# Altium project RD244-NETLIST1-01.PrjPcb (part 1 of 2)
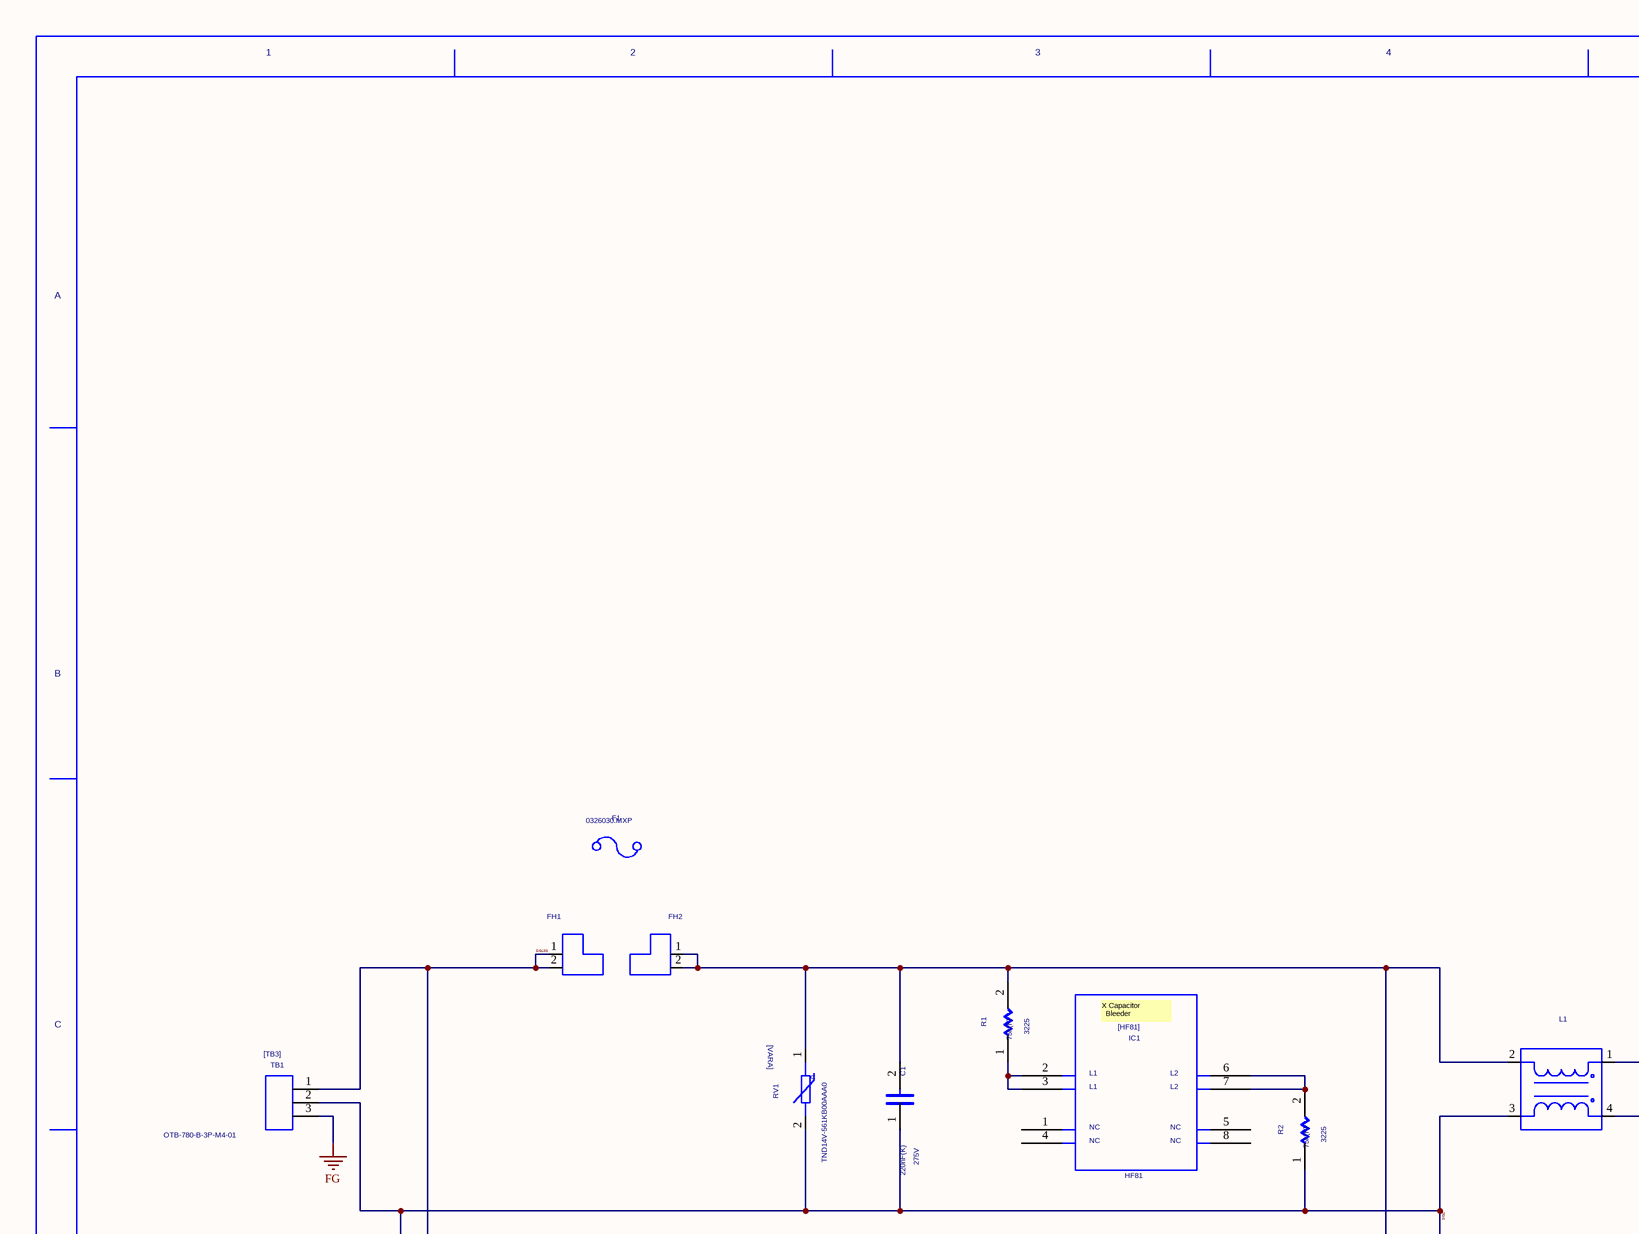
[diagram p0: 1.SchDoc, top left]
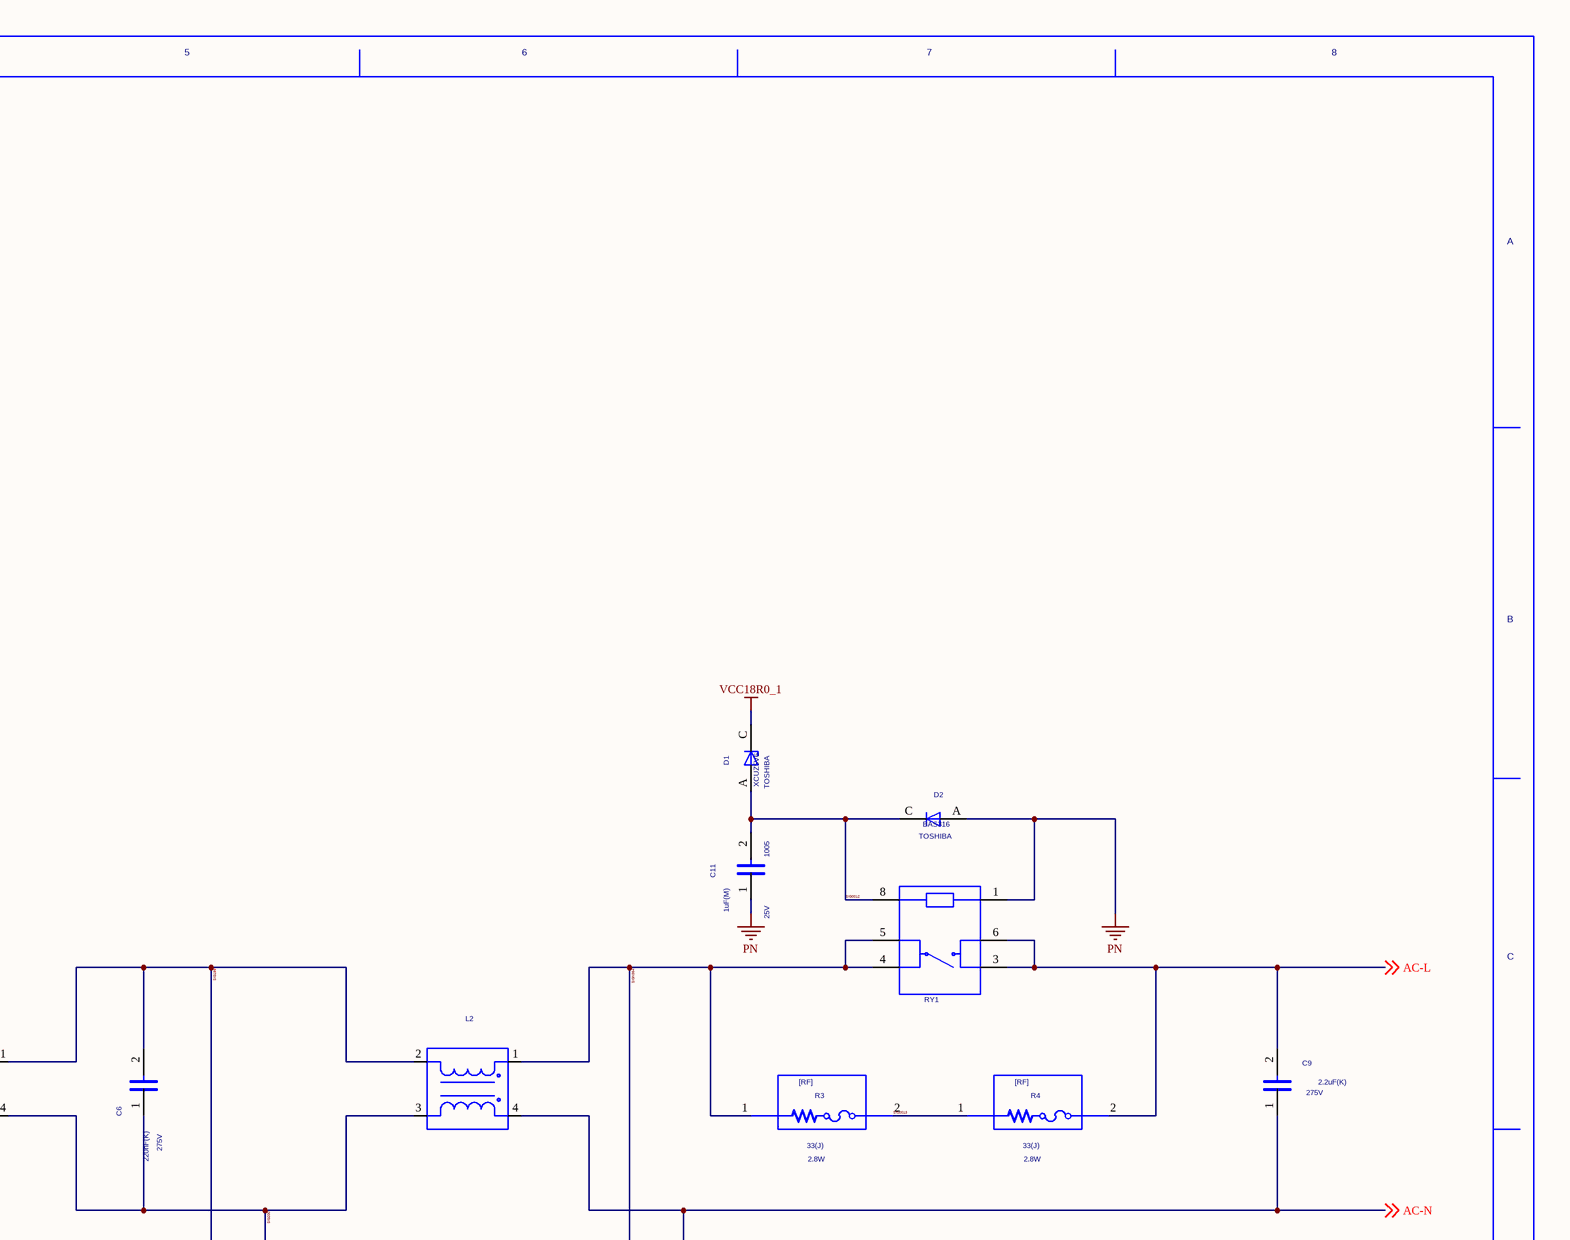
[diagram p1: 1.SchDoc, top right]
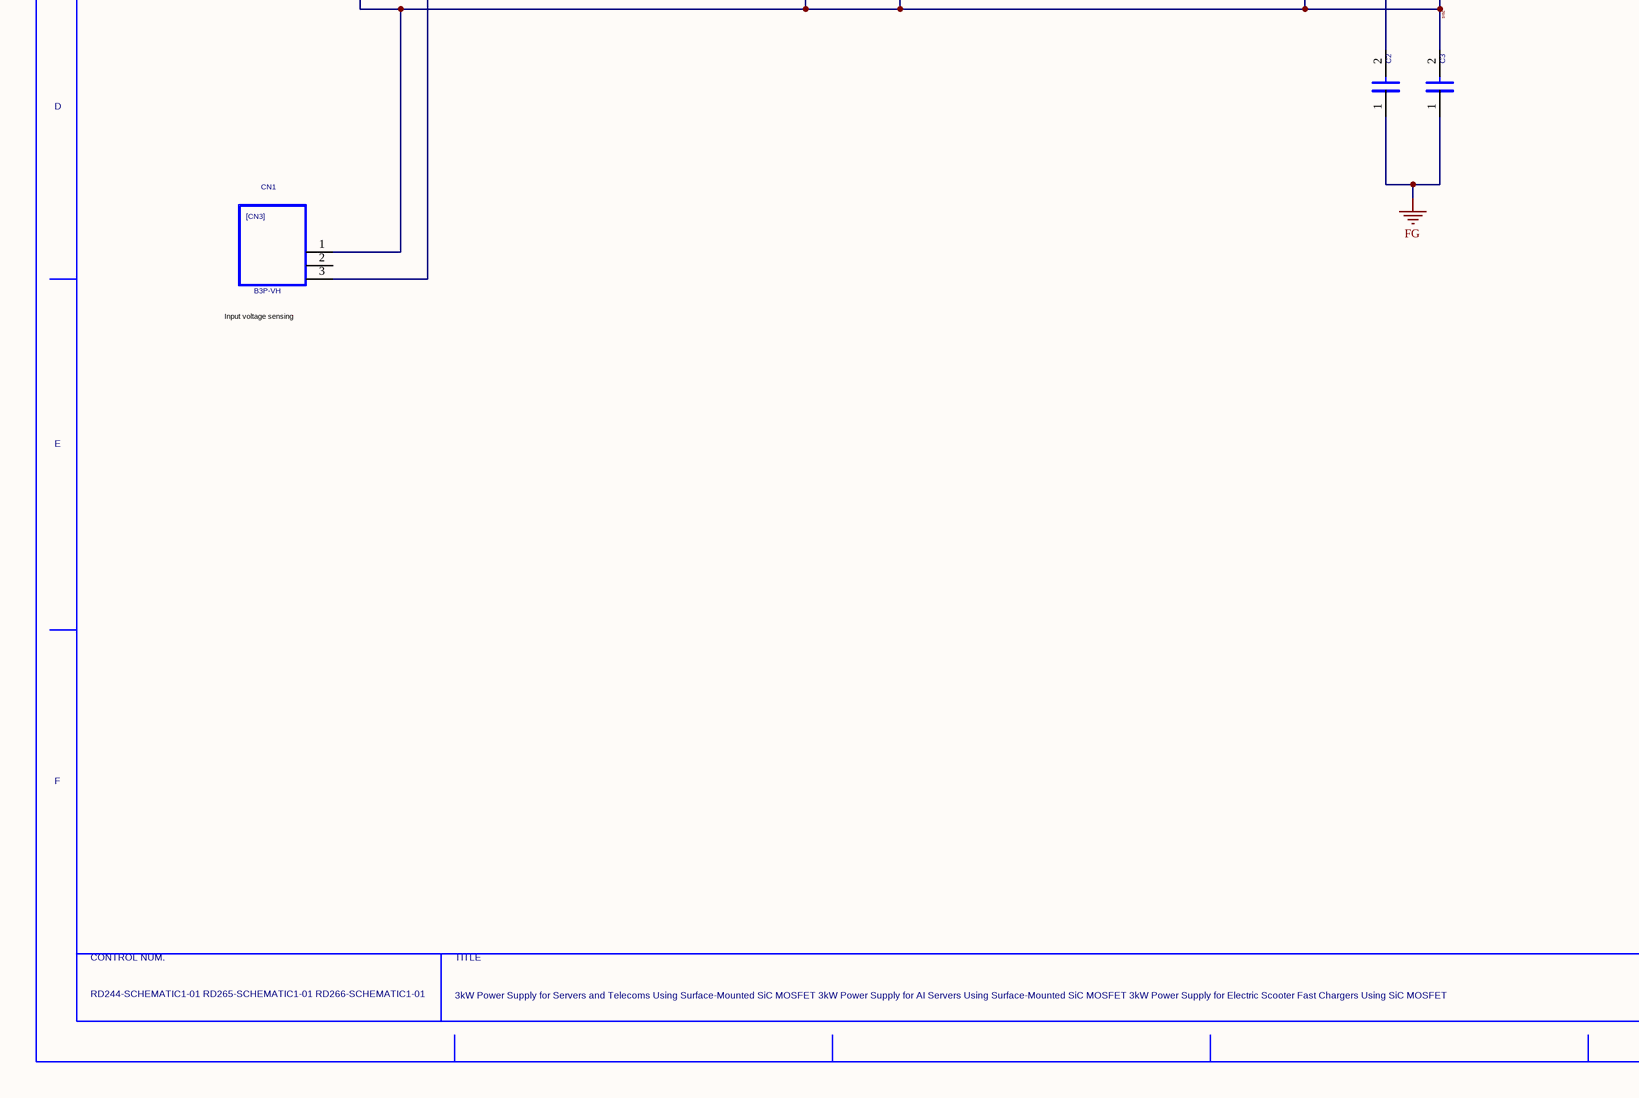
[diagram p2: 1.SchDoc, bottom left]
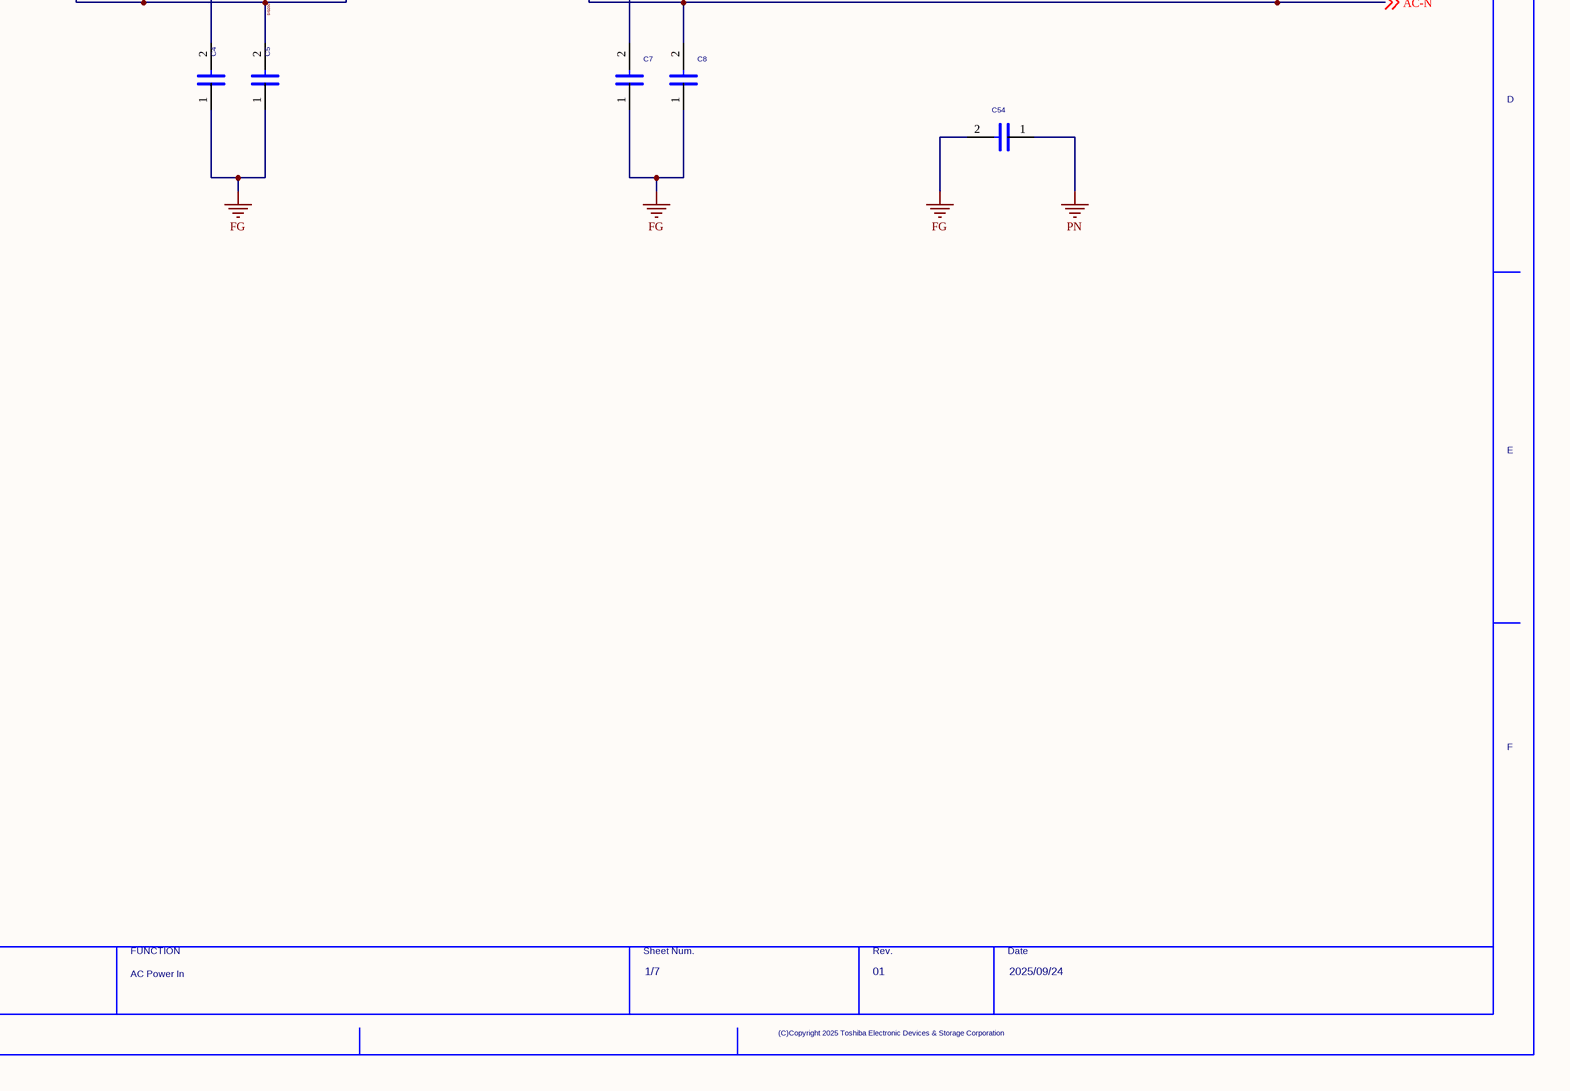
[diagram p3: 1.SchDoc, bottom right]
7 sheets, 392 parts. Net scope: global (net labels, ports and power ports of the same name join across sheets).
Sheets:
  1.SchDoc
  2.SchDoc
  3.SchDoc
  4.SchDoc
  5.SchDoc
  6.SchDoc
  7.SchDoc

## Sheet 1.SchDoc
size 609 x 444 mm

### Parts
(Parts that share a designator on the sheet are numbered #1, #2 ... from top to bottom, then left to right.)
C1  VAL1: 220nF(K)  VAL2: 275V  (hidden comment: C)
C2  DE2B3SA101KA3BT02F  (value not drawn)
C3  DE2B3SA101KA3BT02F  (value not drawn)
C4  DE2E3SA222MN3AT02F  (value not drawn)
C5  DE2E3SA222MN3AT02F  (value not drawn)
C6  VAL1: 220nF(K)  VAL2: 275V  (hidden comment: C)
C7  DE2E3SA222MN3AT02F  (value not drawn)
C8  DE2E3SA222MN3AT02F  (value not drawn)
C9  VAL1: 2.2uF(K)  VAL2: 275V  (hidden comment: C)
C11  VAL1: 1uF(M)  VAL2: 25V  SIZECODESMD: 1005  (hidden comment: C)
C54  DE2B3SA221KA3BT02F  (value not drawn)
CN1  VAL3: B3P-VH  (hidden comment: CN3)
D1  USERCOMPTEXT3: TOSHIBA  VAL3: XCUZ5V6  (hidden comment: ZenerDiode_USC-01)
D2  USERCOMPTEXT3: TOSHIBA  VAL3: BAS316  (hidden comment: D)
F1  (no value)
FH1  01220083Z  (value not drawn)
FH2  01220083Z  (value not drawn)
IC1  VAL3: HF81  (hidden comment: L81)
L1  LDFW021252YBUV0E  (value not drawn)
L2  LDFW021252YBUV0E  (value not drawn)
R1  VAL1: 75k(F)  SIZECODESMD: 3225  (hidden comment: R)
R2  VAL1: 75k(F)  SIZECODESMD: 3225  (hidden comment: R)
R3  VAL1: 33(J)  VAL2: 2.8W  (hidden comment: Y5JA-330JPTL3_5)
R4  VAL1: 33(J)  VAL2: 2.8W  (hidden comment: Y5JA-330JPTL3_5)
RV1  VAL3: TND14V-561KB00AAA0  (hidden comment: VARA)
RY1  G2RL-1A-E2-CV-HA  (value not drawn)
TB1  VAL3: OTB-780-B-3P-M4-01  (hidden comment: TB3)
U?#1  DATE: 2025/09/24  DRAWINGNUMBER: RD244-SCHEMATIC1-01 / RD265-SCHEMATIC1-01 / RD266-SCHEMATIC1-01  TITLE: 3kW Power Supply for Servers and Telecoms Using Surface-Mounted SiC MOSFET / 3kW Power Supply for AI Servers Using Surface-Mounted SiC MOSFET / 3kW Power Supply for Electric Scooter Fast Chargers Using SiC MOSFET  FUNCTION: AC Power In  SHEETNUMBER: 1/7  REVISION: 01  (hidden comment: WAKU_DEF_A3_1)

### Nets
FG: C2.1 C3.1 C4.1 C5.1 C7.1 C8.1 C54.2 TB1.3
PN: C11.1 C54.1 D2.A RY1.1
VCC18R0_1: D1.C
AC-L: C9.2 R4.2 RY1.3 RY1.6 ; off-sheet AC-L
AC-N: C8.2 C9.1 L2.4 ; off-sheet AC-N
SIG1: C1.2 C2.2 FH2.1 FH2.2 L1.2 R1.2 RV1.1
SIG2: C1.1 C3.2 CN1.1 L1.3 R2.1 RV1.2 TB1.2
SIG9: IC1.2 IC1.3 R1.1
SIG10: IC1.6 IC1.7 R2.2
SIG0012: C11.2 D1.A D2.C RY1.8
SIG0013: R3.2 R4.1
SIG193: CN1.3 FH1.1 FH1.2 TB1.1
SIG199: C4.2 C6.2 L1.1 L2.2
SIG200: C5.2 C6.1 L1.4 L2.3
SIGN364: C7.2 L2.1 R3.1 RY1.4 RY1.5

Not connected (* = marked no-connect by the designer): CN1 2; IC1 1 4 5 8

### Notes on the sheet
- (near CN1) Input voltage sensing

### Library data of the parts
C1 C6 = C_Dup2: OriginalSymbolOrigin: (2540,7620); COMP: PRT_17; MAXGCOUNT: 1; SIZECODESMD: DIP; SAVECOUNT: 0
C2 C3 = DE2B3SA101KA3BT02F: VAL1: 100pF; VAL2: 250V; TIME: 18:06:52; UPDATEUSER: t6860224; SAVECOUNT: 1; OriginalSymbolOrigin: (2540,7620); SIZECODESMD: DIP; CHIPSIZE: リードピッチ7.5mm品希望
C4 C7 C8 = DE2E3SA222MN3AT02F: VAL1: 2.2nF(M); VAL2: 250V; TIME: 18:04:40; UPDATEUSER: t6860224; UPDATETIME: 18:05:46; SAVECOUNT: 2; OriginalSymbolOrigin: (2540,7620); CHIPSIZE: リードピッチ7.5mm品希望; MAXGCOUNT: 1; SIZECODESMD: DIP
C5 = DE2E3SA222MN3AT02F: SQ_PART_MODEL: CON_2.2N; VAL1: 2.2nF(M); VAL2: 250V; TIME: 18:04:40; UPDATEUSER: t6860224; UPDATETIME: 18:05:46; SAVECOUNT: 2; OriginalSymbolOrigin: (2540,7620); CHIPSIZE: リードピッチ7.5mm品希望; MAXGCOUNT: 1; SIZECODESMD: DIP; ADSCNVFLAG: ON
C9 = C_Dup2: OriginalSymbolOrigin: (2540,7620); COMP: PRT_18; MAXGCOUNT: 1; SIZECODESMD: DIP; SAVECOUNT: 0
C11 = C_Dup2: OriginalSymbolOrigin: (2540,7620); COMP: PRT_52; MAXGCOUNT: 1; SAVECOUNT: 0
C54 = DE2B3SA221KA3BT02F: VAL1: 220pF(K); VAL2: 250V; TIME: 18:06:26; UPDATEUSER: t6860224; SAVECOUNT: 1; OriginalSymbolOrigin: (2540,7620); SIZECODESMD: DIP
CN1 = CN3: OriginalSymbolOrigin: (2540,17780); USERCOMPTEXT3: ローカライズ; COMPONENTNAME: G36220401068_package; MAXGCOUNT: 1; COMP: G36220401068; ADSCNVFLAG: ON; SAVECOUNT: 0
D1 = ZENERDIODE_USC-01: SAVEAREA0: -4630,-153,17114,13055; TIME: 14:49:55; UPDATEUSER: t4887876; UPDATETIME: 08:23:49; SAVECOUNT: 9; VAL1: 5.6V; OriginalSymbolOrigin: (5080,5080); MAXGCOUNT: 1; ADSCNVFLAG: ON; ADSCOMPONENTNAME: D_ZD
D2 = D_Dup1: SAVEAREA0: -225,-91,12804,7836; SAVECOUNT: 3; TIME: 14:49:55; UPDATEUSER: 19870035; UPDATETIME: 14:20:16; OriginalSymbolOrigin: (5080,5080); USERCOMPTEXT2: 100V,0.25A; COMP: PRT_26; MAXGCOUNT: 1
F1 = 0326030.MXP: PCBCELLNAME: F; SAVECOUNT: 7; SAVEAREA0: -525,-4690,15446,5013; DEVICENAME: F0805B2R00FWTR; VAL1: 250VAC; VAL2: 30A SlowBlow; TIME: 10:50:48; UPDATEUSER: t4887876; UPDATETIME: 10:51:07; OriginalSymbolOrigin: (3048,3166)
FH1 FH2 = 01220083Z: VAL1: 250V; VAL2: 30A; TIME: 10:48:22; UPDATEUSER: t4887876; UPDATETIME: 10:49:44; SAVECOUNT: 3; OriginalSymbolOrigin: (7620,10160)
IC1 = L81: SAVEAREA0: -12429,-3512,55842,41521; TIME: 18:31:00; UPDATEUSER: cae; UPDATETIME: 11:10:50; SAVECOUNT: 13; OriginalSymbolOrigin: (7620,35560); COMP: PRT_45
L1 L2 = LDFW021252YBUV0E: DEVICENAME: DLW21HN670SQ2; SAVEAREA0: -21350,-26515,41553,39372; TIME: 11:39:40; UPDATEUSER: t4887876; UPDATETIME: 20:09:21; SAVECOUNT: 7; VAL1: 8.1mH; VAL2: 21A; OriginalSymbolOrigin: (2540,12700)
R1 R2 = R_Dup2: VAL2: 500mW; OriginalSymbolOrigin: (5080,5080); COMP: PRT_23; MAXGCOUNT: 1; SAVECOUNT: 0
R3 R4 = Y5JA-330JPTL3_5: TIME: 16:26:39; UPDATEUSER: t4887876; UPDATETIME: 20:40:35; SAVECOUNT: 5; OriginalSymbolOrigin: (-1270,12700); MAXGCOUNT: 1; CHIPSIZE: 13x9xH25.5
RV1 = VARA: SAVEAREA0: -9950,-8554,25168,13619; SAVECOUNT: 12; TIME: 09:56:50; UPDATEUSER: tomizawa-y; OriginalSymbolOrigin: (2540,5080); COMP: PRT_37; VAL1: 560V; MAXGCOUNT: 1
RY1 = G2RL-1A-E2-CV-HA: TIME: 17:19:14; UPDATEUSER: t4887876; UPDATETIME: 19:21:58; SAVECOUNT: 7; COMP: G2RL-1A-E2-CV-HA_DC12; OriginalSymbolOrigin: (5080,20320); USERCOMPTEXT1: 23A; MAXGCOUNT: 1; SAVEAREA0: -9347,-440,34039,23986
TB1 = TB3: SAVEAREA0: -8260,-205,20967,17940; TIME: 13:41:39; UPDATEUSER: 19990028; UPDATETIME: 11:31:50; SAVECOUNT: 4; OriginalSymbolOrigin: (2540,12700); USERCOMPTEXT3: ローカライズ; MAXGCOUNT: 1; COMP: K29S000A; ADSCNVFLAG: ON
U?#1 = WAKU_DEF_A3_1: PLOTTIME: HH:MM; SAVEAREA0: 96913,-567914,509243,-368858; TIME: 10:19:22; UPDATEUSER: t5459927; UPDATETIME: 13:12:48; SAVECOUNT: 3; ZONEOFFSETX: 36; ZONEOFFSETY: -24; OriginalSymbolOrigin: (12700,-12700); SHTSAVECOUNT: 118; PAGENUMBER: 1; DESIGNED: TOSHIBA

## Sheet 2.SchDoc
size 609 x 444 mm
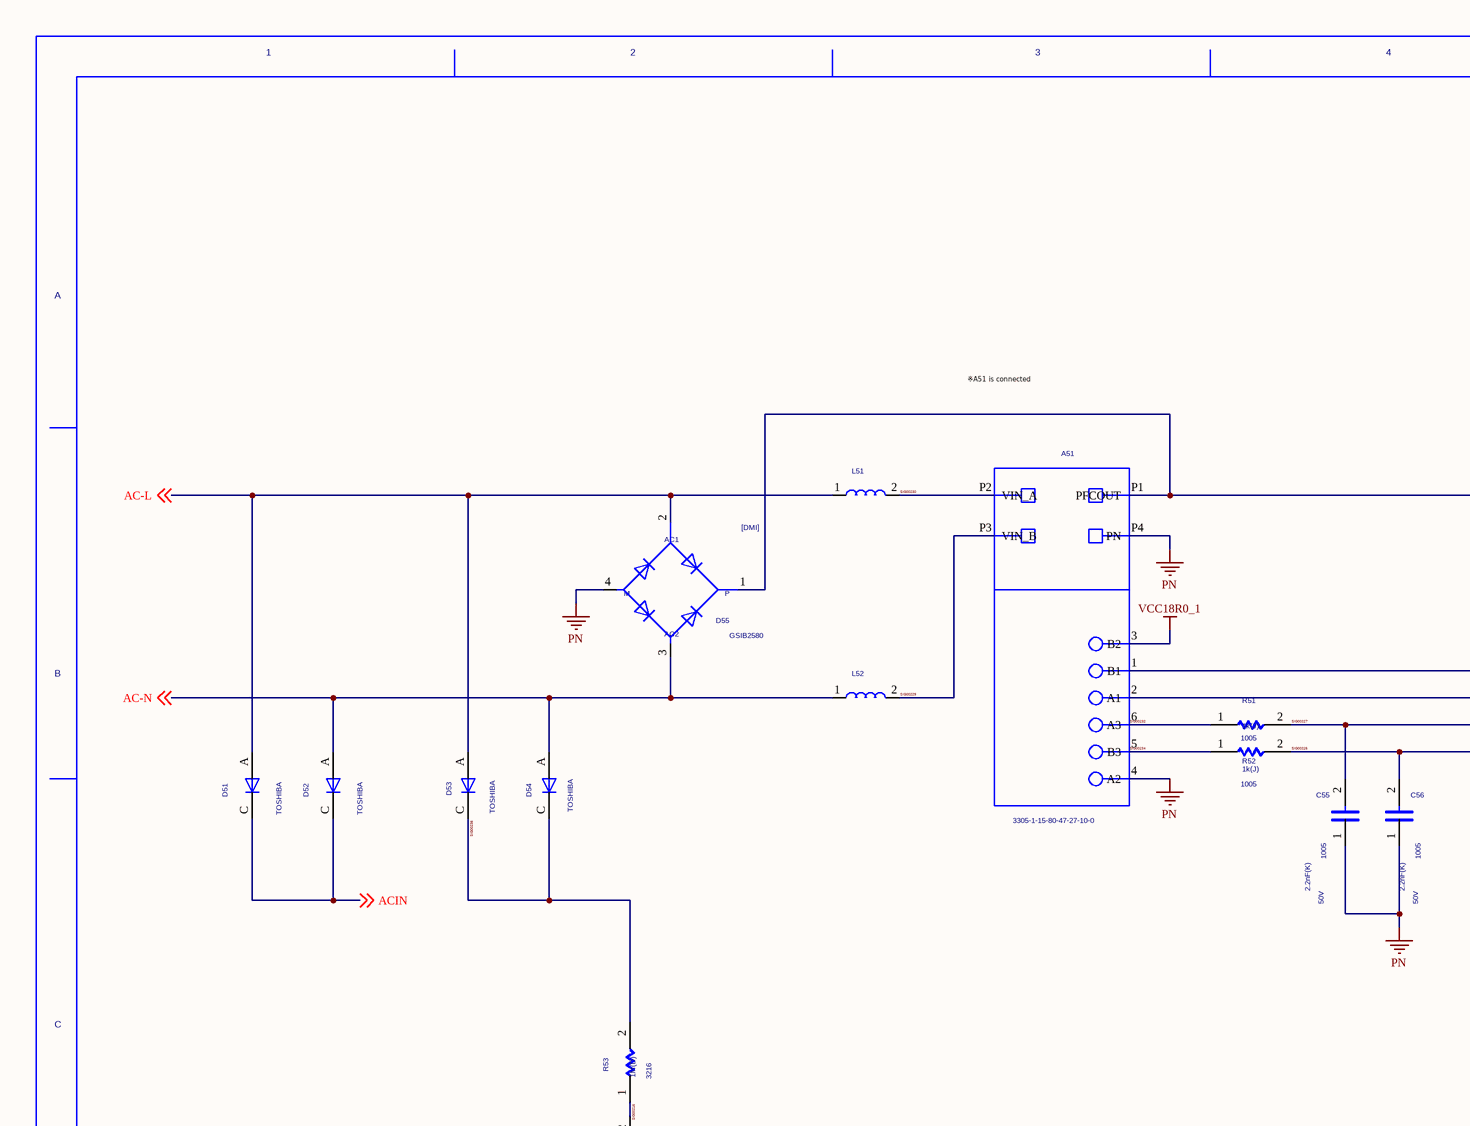
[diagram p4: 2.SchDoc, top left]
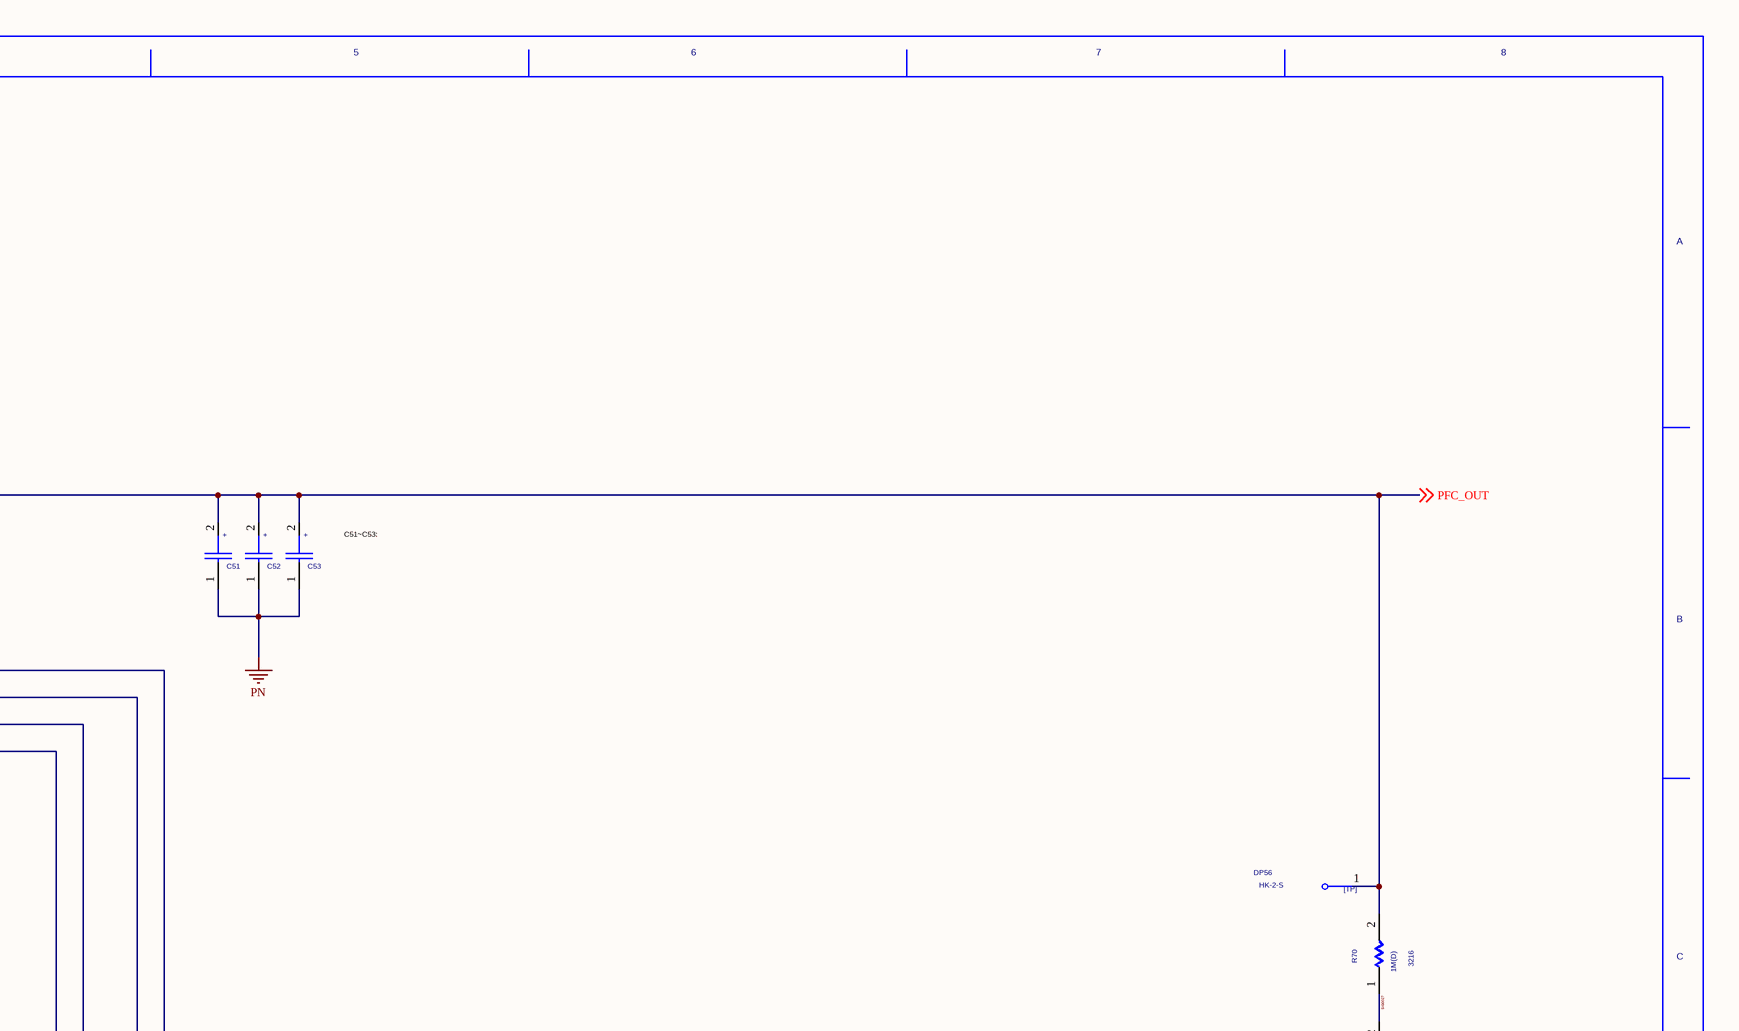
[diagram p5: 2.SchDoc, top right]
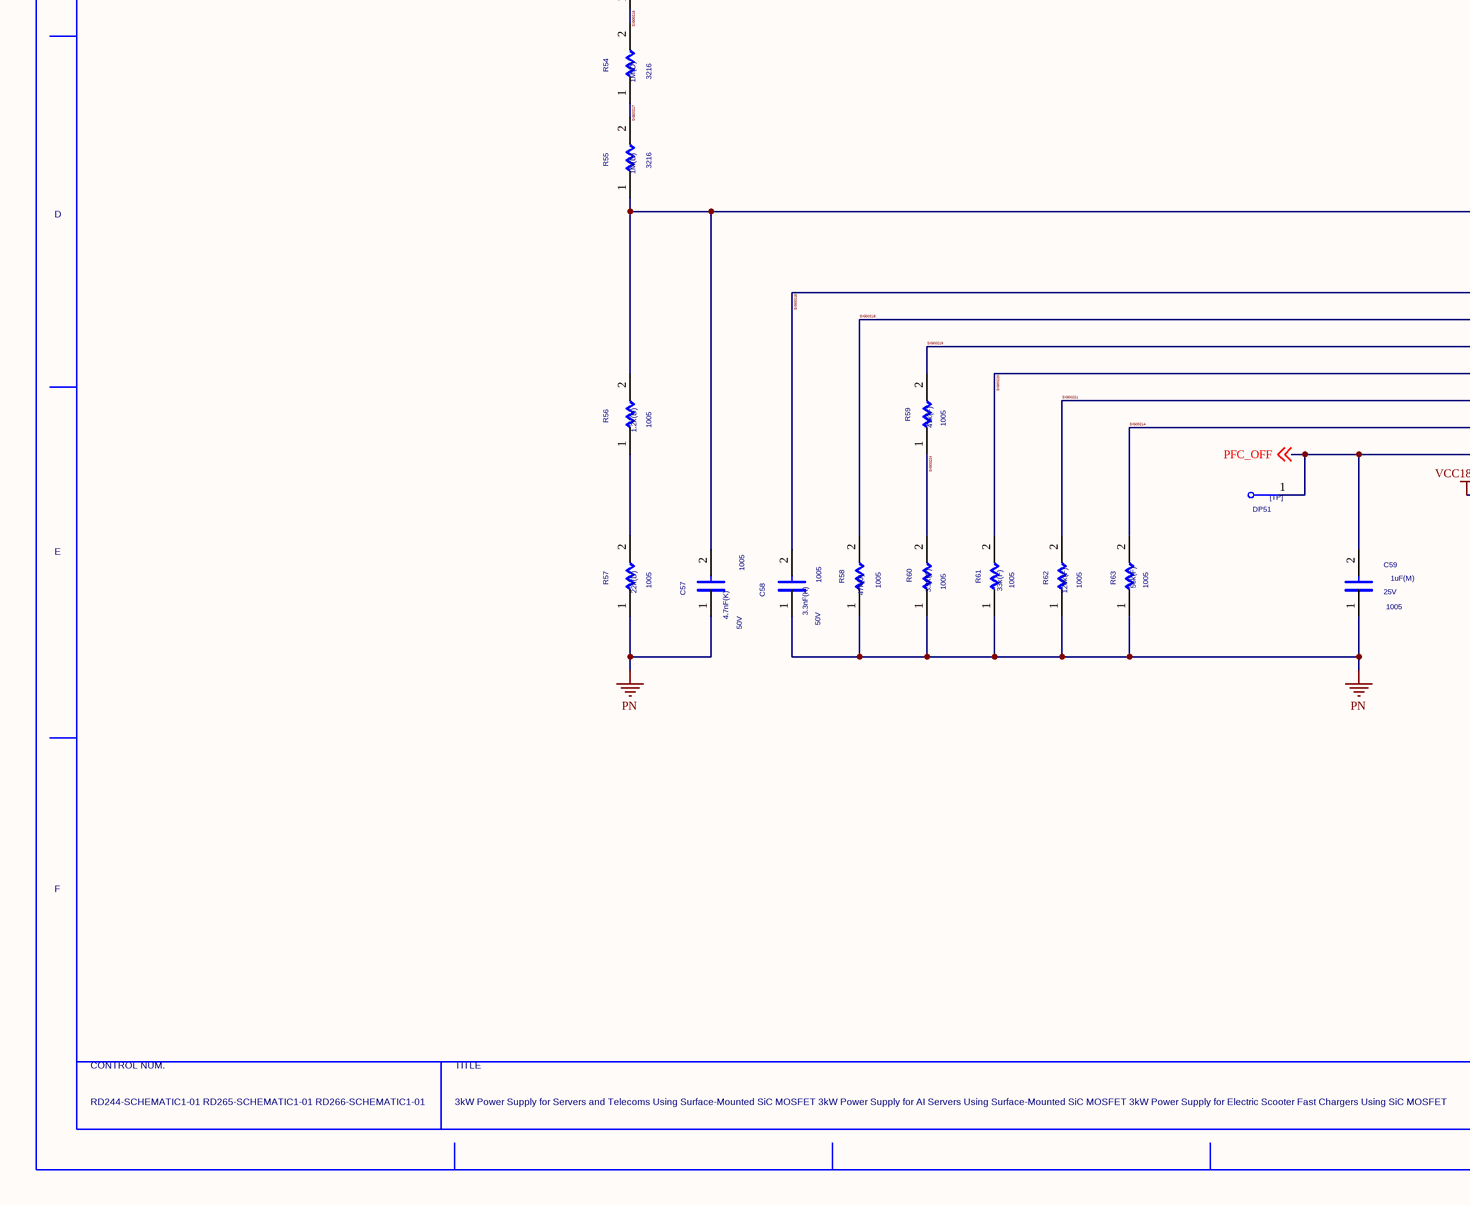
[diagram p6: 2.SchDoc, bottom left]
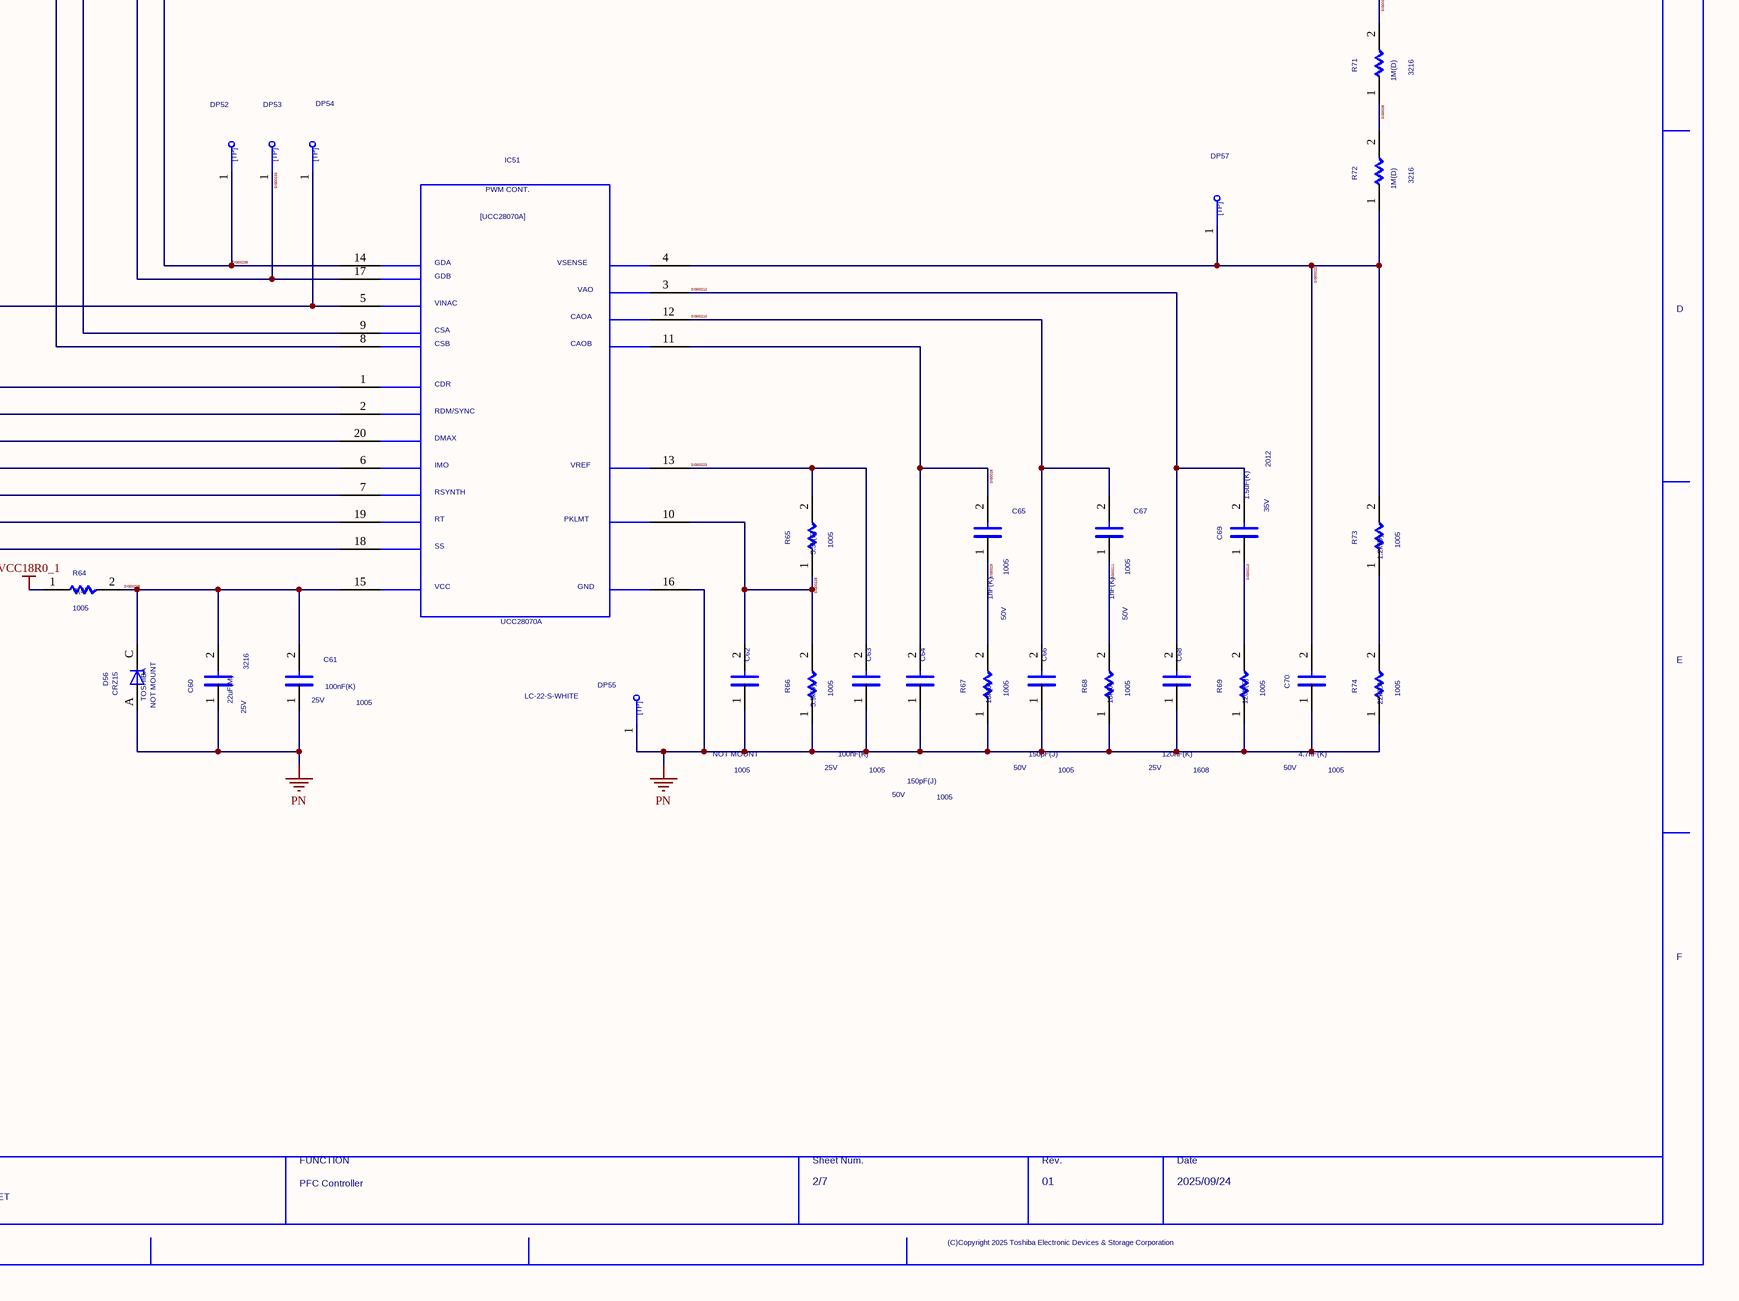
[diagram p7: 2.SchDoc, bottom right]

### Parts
(Parts that share a designator on the sheet are numbered #1, #2 ... from top to bottom, then left to right.)
A51  VAL3: 3305-1-15-80-47-27-10-0  (hidden comment: RD-244_PFC_UNIT1)
C51  EKHE421VSN102MA45Z  (value not drawn)
C52  EKHE421VSN102MA45Z  (value not drawn)
C53  EKHE421VSN102MA45Z  (value not drawn)
C55  VAL1: 2.2nF(K)  VAL2: 50V  SIZECODESMD: 1005  (hidden comment: C)
C56  VAL1: 2.2nF(K)  VAL2: 50V  SIZECODESMD: 1005  (hidden comment: C)
C57  VAL1: 4.7nF(K)  VAL2: 50V  SIZECODESMD: 1005  (hidden comment: C)
C58  VAL1: 3.3nF(K)  VAL2: 50V  SIZECODESMD: 1005  (hidden comment: C)
C59  VAL1: 1uF(M)  VAL2: 25V  SIZECODESMD: 1005  (hidden comment: C)
C60  VAL1: 22uF(M)  VAL2: 25V  SIZECODESMD: 3216  (hidden comment: C)
C61  VAL1: 100nF(K)  VAL2: 25V  SIZECODESMD: 1005  (hidden comment: C)
C62  NOTMOUNT: NOT MOUNT  SIZECODESMD: 1005  (hidden comment: C)
C63  VAL1: 100nF(K)  VAL2: 25V  SIZECODESMD: 1005  (hidden comment: C)
C64  VAL1: 150pF(J)  VAL2: 50V  SIZECODESMD: 1005  (hidden comment: C)
C65  VAL1: 1nF(K)  VAL2: 50V  SIZECODESMD: 1005  (hidden comment: C)
C66  VAL1: 150pF(J)  VAL2: 50V  SIZECODESMD: 1005  (hidden comment: C)
C67  VAL1: 1nF(K)  VAL2: 50V  SIZECODESMD: 1005  (hidden comment: C)
C68  VAL1: 120nF(K)  VAL2: 25V  SIZECODESMD: 1608  (hidden comment: C)
C69  VAL1: 1.5uF(K)  VAL2: 35V  SIZECODESMD: 2012  (hidden comment: GRM21BC71E106KE01)
C70  VAL1: 4.7nF(K)  VAL2: 50V  SIZECODESMD: 1005  (hidden comment: C)
D51  USERCOMPTEXT3: TOSHIBA  (hidden comment: CRG04A)
D52  USERCOMPTEXT3: TOSHIBA  (hidden comment: CRG04A)
D53  USERCOMPTEXT3: TOSHIBA  (hidden comment: CRG04A)
D54  USERCOMPTEXT3: TOSHIBA  (hidden comment: CRG04A)
D55  VAL3: GSIB2580  (hidden comment: DMI)
D56  NOTMOUNT: NOT MOUNT  USERCOMPTEXT3: TOSHIBA  VAL3: CRZ15  (hidden comment: ZD)
DP51  TP  (value not drawn)
DP52  TP  (value not drawn)
DP53  TP  (value not drawn)
DP54  TP  (value not drawn)
DP55  VAL3: LC-22-S-WHITE  (hidden comment: TP)
DP56  VAL3: HK-2-S  (hidden comment: TP)
DP57  TP  (value not drawn)
IC51  VAL3: UCC28070A  (hidden comment: L28070)
L51  TAM-30A131  (value not drawn)
L52  TAM-30A131  (value not drawn)
R51  VAL1: 1k(J)  SIZECODESMD: 1005  (hidden comment: R)
R52  VAL1: 1k(J)  SIZECODESMD: 1005  (hidden comment: R)
R53  VAL1: 1M(D)  SIZECODESMD: 3216  (hidden comment: R)
R54  VAL1: 1M(D)  SIZECODESMD: 3216  (hidden comment: R)
R55  VAL1: 1M(D)  SIZECODESMD: 3216  (hidden comment: R)
R56  VAL1: 1.2k(D)  SIZECODESMD: 1005  (hidden comment: R)
R57  VAL1: 22k(D)  SIZECODESMD: 1005  (hidden comment: R)
R58  VAL1: 47k(J)  SIZECODESMD: 1005  (hidden comment: R)
R59  VAL1: 47k(F)  SIZECODESMD: 1005  (hidden comment: R)
R60  VAL1: 3.3k(F)  SIZECODESMD: 1005  (hidden comment: R)
R61  VAL1: 33k(F)  SIZECODESMD: 1005  (hidden comment: R)
R62  VAL1: 120k(F)  SIZECODESMD: 1005  (hidden comment: R)
R63  VAL1: 56k(F)  SIZECODESMD: 1005  (hidden comment: R)
R64  VAL1: 1(J)  SIZECODESMD: 1005  (hidden comment: R)
R65  VAL1: 3.3k(F)  SIZECODESMD: 1005  (hidden comment: R)
R66  VAL1: 3.9k(J)  SIZECODESMD: 1005  (hidden comment: R)
R67  VAL1: 18k(J)  SIZECODESMD: 1005  (hidden comment: R)
R68  VAL1: 18k(J)  SIZECODESMD: 1005  (hidden comment: R)
R69  VAL1: 120k(F)  SIZECODESMD: 1005  (hidden comment: R)
R70  VAL1: 1M(D)  SIZECODESMD: 3216  (hidden comment: R)
R71  VAL1: 1M(D)  SIZECODESMD: 3216  (hidden comment: R)
R72  VAL1: 1M(D)  SIZECODESMD: 3216  (hidden comment: R)
R73  VAL1: 1.2k(D)  SIZECODESMD: 1005  (hidden comment: R)
R74  VAL1: 22k(D)  SIZECODESMD: 1005  (hidden comment: R)
U?#2  DATE: 2025/09/24  DRAWINGNUMBER: RD244-SCHEMATIC1-01 / RD265-SCHEMATIC1-01 / RD266-SCHEMATIC1-01  TITLE: 3kW Power Supply for Servers and Telecoms Using Surface-Mounted SiC MOSFET / 3kW Power Supply for AI Servers Using Surface-Mounted SiC MOSFET / 3kW Power Supply for Electric Scooter Fast Chargers Using SiC MOSFET  FUNCTION: PFC Controller  SHEETNUMBER: 2/7  REVISION: 01  (hidden comment: WAKU_DEF_A3_1)

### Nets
PN: A51.4(A2) A51.P4(PN) C51.1 C52.1 C53.1 C55.1 C56.1 C57.1 C58.1 C59.1 C60.1 C61.1 C62.1 C63.1 C64.1 C66.1 C68.1 C70.1 D55.4 D56.A DP55.1 IC51.16 R57.1 R58.1 R60.1 R61.1 R62.1 R63.1 R66.1 R67.1 R68.1 R69.1 R74.1
VCC18R0_1: A51.3(B2) R64.1
$BN000001: R73.1 R74.2
$BN000002: R56.1 R57.2
AC-L: D51.A D53.A D55.2 L51.1 ; off-sheet AC-L
AC-N: D52.A D54.A D55.3 L52.1 ; off-sheet AC-N
ACIN: D51.C D52.C ; off-sheet ACIN
PFC_OFF: C59.2 DP51.1 IC51.18 ; off-sheet PFC_OFF
PFC_OUT: A51.P1(PFCOUT) C51.2 C52.2 C53.2 D55.1 DP56.1 R70.2 ; off-sheet PFC_OUT
SIG0026: R71.1 R72.2
SIG0027: R70.1 R71.2
SIG0028: C64.2 C65.2 IC51.11
SIG0029: C65.1 R67.2
SIG62: C57.2 DP54.1 IC51.5 R55.1 R56.2
SIG00210: C66.2 C67.2 IC51.12
SIG00211: C67.1 R68.2
SIG00212: C68.2 C69.2 IC51.3
SIG00213: C69.1 R69.2
SIG00214: IC51.19 R63.2
SIG00215: IC51.2 R58.2
SIG00216: R53.1 R54.2
SIG00217: R54.1 R55.2
SIG00218: C58.2 IC51.1
SIG00219: IC51.20 R59.2
SIG00220: IC51.6 R61.2
SIG00221: IC51.7 R62.2
SIG00222: C70.2 DP57.1 IC51.4 R72.1 R73.2
SIG00223: C63.2 IC51.13 R65.2
SIG00224: R59.1 R60.2
SIG00225: C62.2 IC51.10 R65.1 R66.2
SIG00226: C56.2 IC51.8 R52.2
SIG00227: C55.2 IC51.9 R51.2
SIG00228: C60.2 C61.2 D56.C IC51.15 R64.2
SIG00229: A51.P3(VIN_B) L52.2
SIG00230: A51.P2(VIN_A) L51.2
SIG00232: A51.6(A3) R51.1
SIG00233: A51.2(A1) DP53.1 IC51.17
SIG00234: A51.5(B3) R52.1
SIG00235: A51.1(B1) DP52.1 IC51.14
SIG00236: D53.C D54.C R53.2

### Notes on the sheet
- ※A51 is connected
  to CN601 and CN602 of RD244-SCHEMATICS2
- (near C53) C51~C53:

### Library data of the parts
A51 = RD-244_PFC_UNIT1: TIME: 11:34:46; UPDATEUSER: t5459927; UPDATETIME: 16:41:12; SAVECOUNT: 29; SAVEAREA0: -20981,-344,43891,33349; OriginalSymbolOrigin: (0,63500)
C51-C53 = EKHE421VSN102MA45Z: SQ_PART_MODEL: CON_390U; SAVEAREA0: -1450,-153,20294,13055; SAVECOUNT: 53; TIME: 15:02:55; UPDATEUSER: t4887876; UPDATETIME: 08:41:08; VAL1: 420V; VAL2: 1010uF(M); OriginalSymbolOrigin: (2540,10160); MAXGCOUNT: 1; SIZECODESMD: DIP; ADSCNVFLAG: ON
C55 C57-C59 C63-C67 C70 = C_Dup2: as C11 on sheet 1
C56 = C_Dup2: OriginalSymbolOrigin: (2540,7620); COMP: PRT_52; OLDCOMPONENTID: 99; MAXGCOUNT: 1; SAVECOUNT: 0
C60 = C_Dup1: OriginalSymbolOrigin: (2540,7620); COMP: PRT_46; SAVECOUNT: 0
C61 = C_Dup2: SQ_PART_MODEL: CON_100N; OriginalSymbolOrigin: (2540,7620); COMP: PRT_52; MAXGCOUNT: 1; ADSCNVFLAG: ON; ADSCOMPONENTNAME: C_1005; SAVECOUNT: 0
C62 = C_Dup2: VAL1: 100nF(K); VAL2: 25V; OriginalSymbolOrigin: (2540,7620); COMP: PRT_52; MAXGCOUNT: 1; SAVECOUNT: 0
C68 = C_Dup2: OriginalSymbolOrigin: (2540,7620); COMP: PRT_48; MAXGCOUNT: 1; SAVECOUNT: 0
C69 = GRM21BC71E106KE01: TIME: 10:25:11; UPDATEUSER: t4887876; UPDATETIME: 16:23:00; SAVECOUNT: 11; MAKER: Murata; OriginalSymbolOrigin: (2540,7620); CHIPSIZE: 1005; MAXGCOUNT: 1
D51-D54 = CRG04A: SAVEAREA0: -4630,-153,17114,13055; TIME: 14:49:55; UPDATEUSER: t6860224; UPDATETIME: 10:39:47; SAVECOUNT: 14; MAXV: 600V; MAXI: 1A; OriginalSymbolOrigin: (5080,5080); USERCOMPTEXT2: 600V,1A; MAXGCOUNT: 1
D55 = DMI: SAVECOUNT: 7; SAVEAREA0: -7762,-358,32649,26224; TIME: 10:09:47; UPDATEUSER: fukuda-y; UPDATETIME: 17:30:39; OriginalSymbolOrigin: (0,25400); COMP: PRT_53; MAXGCOUNT: 1
D56 = ZD: SAVEAREA0: -4630,-153,17114,13055; TIME: 14:49:55; UPDATEUSER: fukuda-y; UPDATETIME: 08:18:42; SAVECOUNT: 6; OriginalSymbolOrigin: (5080,5080); COMP: PRT_6; MAXGCOUNT: 1
DP51-DP54 DP57 = TP: TIME: 16:12:21; UPDATEUSER: fukuda-y; UPDATETIME: 16:18:11; SAVECOUNT: 2; SAVEAREA0: -242,-92,12810,7836; OriginalSymbolOrigin: (0,7620); USERCOMPTEXT1: Φ1.5mm; COMP: DTP815
DP55 = TP: TIME: 16:12:21; UPDATEUSER: fukuda-y; UPDATETIME: 16:18:11; SAVECOUNT: 2; SAVEAREA0: -242,-92,12810,7836; OriginalSymbolOrigin: (0,7620); COMP: PRT_49
DP56 = TP: TIME: 16:12:21; UPDATEUSER: fukuda-y; UPDATETIME: 16:18:11; SAVECOUNT: 2; SAVEAREA0: -242,-92,12810,7836; OriginalSymbolOrigin: (0,7620); COMP: PRT_44
IC51 = L28070: SAVEAREA0: -12344,-1037,78634,87348; SAVECOUNT: 29; TIME: 15:02:55; UPDATEUSER: cae; UPDATETIME: 14:36:12; OriginalSymbolOrigin: (7620,83820); COMP: PRT_59
L51 L52 = TAM-30A131: VAL1: 100uH min.; VAL2: 30A; TIME: 14:26:02; UPDATEUSER: t4887876; SAVECOUNT: 1; OriginalSymbolOrigin: (2540,5080)
R51 = R_Dup2: VAL2: 63mW; OriginalSymbolOrigin: (5080,5080); COMP: GDM010004481; CHIPSIZE: 1608; OLDCOMPONENTID: 100; MAXGCOUNT: 1; SAVECOUNT: 0
R52 R57 R58 R61 R63 R64 R67-R69 R74 = R_Dup2: VAL2: 63mW; OriginalSymbolOrigin: (5080,5080); COMP: GDM010004481; CHIPSIZE: 1608; MAXGCOUNT: 1; SAVECOUNT: 0
R53-R55 R70-R72 = R_Dup2: VAL2: 250mW; OriginalSymbolOrigin: (5080,5080); COMP: PRT_5; CHIPSIZE: 1608; MAXGCOUNT: 1; SAVECOUNT: 0
R56 R59 R60 R62 R65 R66 R73 = R_Dup2: VAL2: 63mW; OriginalSymbolOrigin: (5080,5080); MAXGCOUNT: 1; COMP: GDM010004481; CHIPSIZE: 1608; SAVECOUNT: 0
U?#2 = WAKU_DEF_A3_1: PLOTTIME: HH:MM; SAVEAREA0: 96913,-567914,509243,-368858; TIME: 14:20:16; UPDATEUSER: t5459927; UPDATETIME: 13:12:48; SAVECOUNT: 3; ZONEOFFSETX: 36; ZONEOFFSETY: -24; OriginalSymbolOrigin: (12700,-12700); SHTSAVECOUNT: 140; PAGENUMBER: 2; DESIGNED: TOSHIBA

## Sheet 3.SchDoc
size 609 x 444 mm
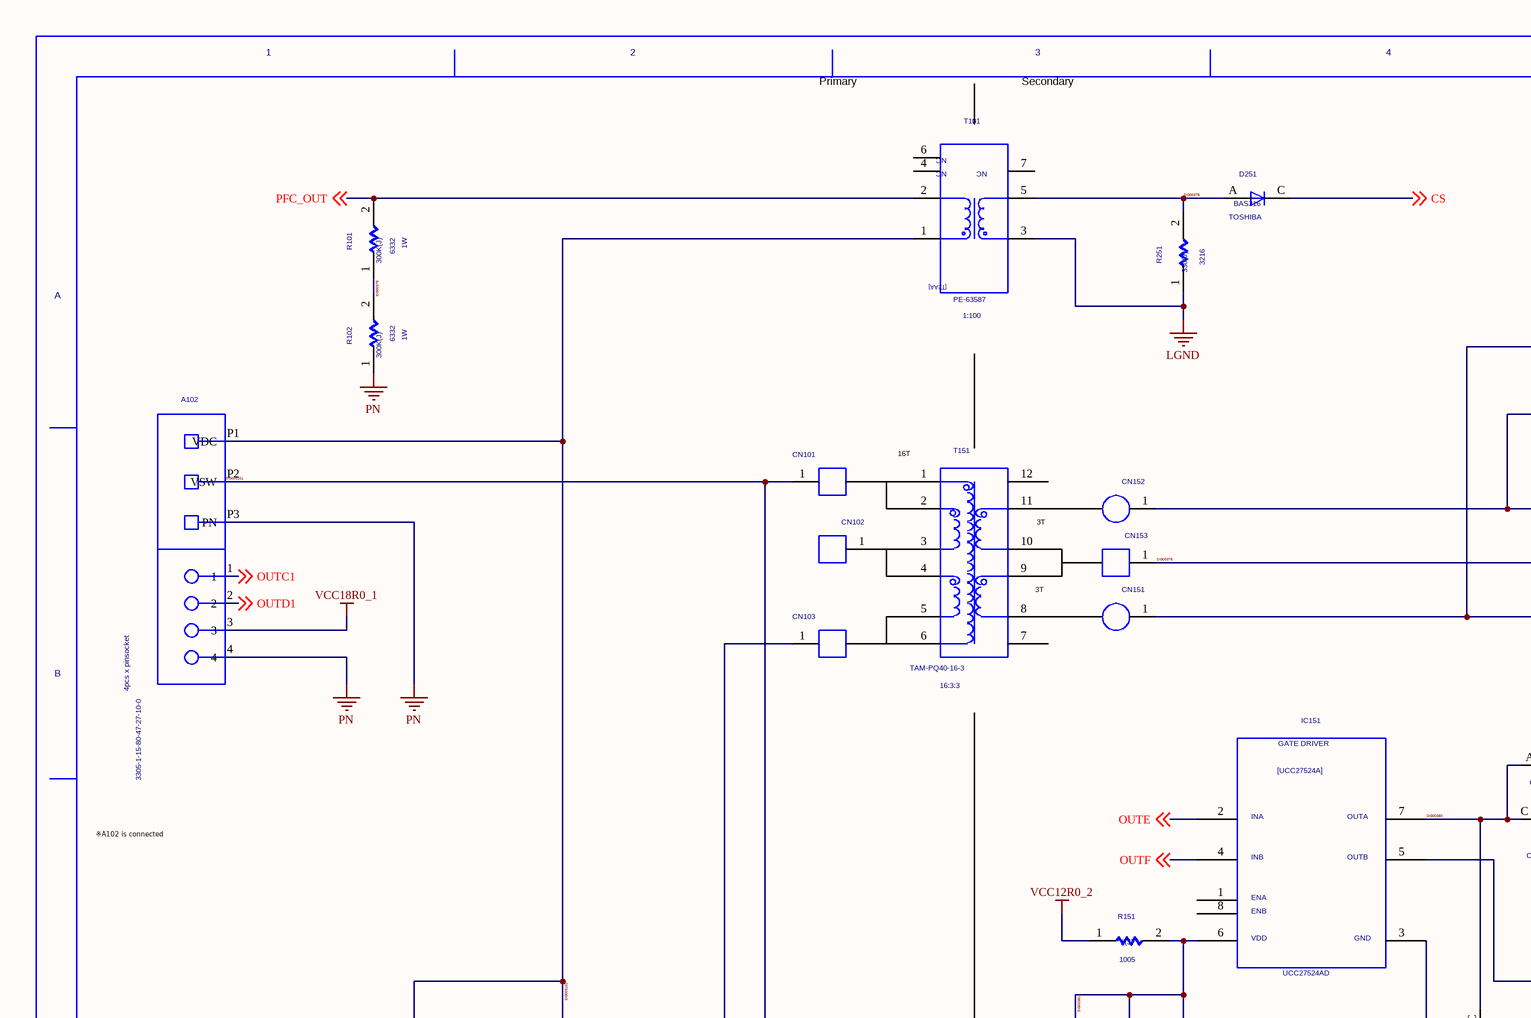
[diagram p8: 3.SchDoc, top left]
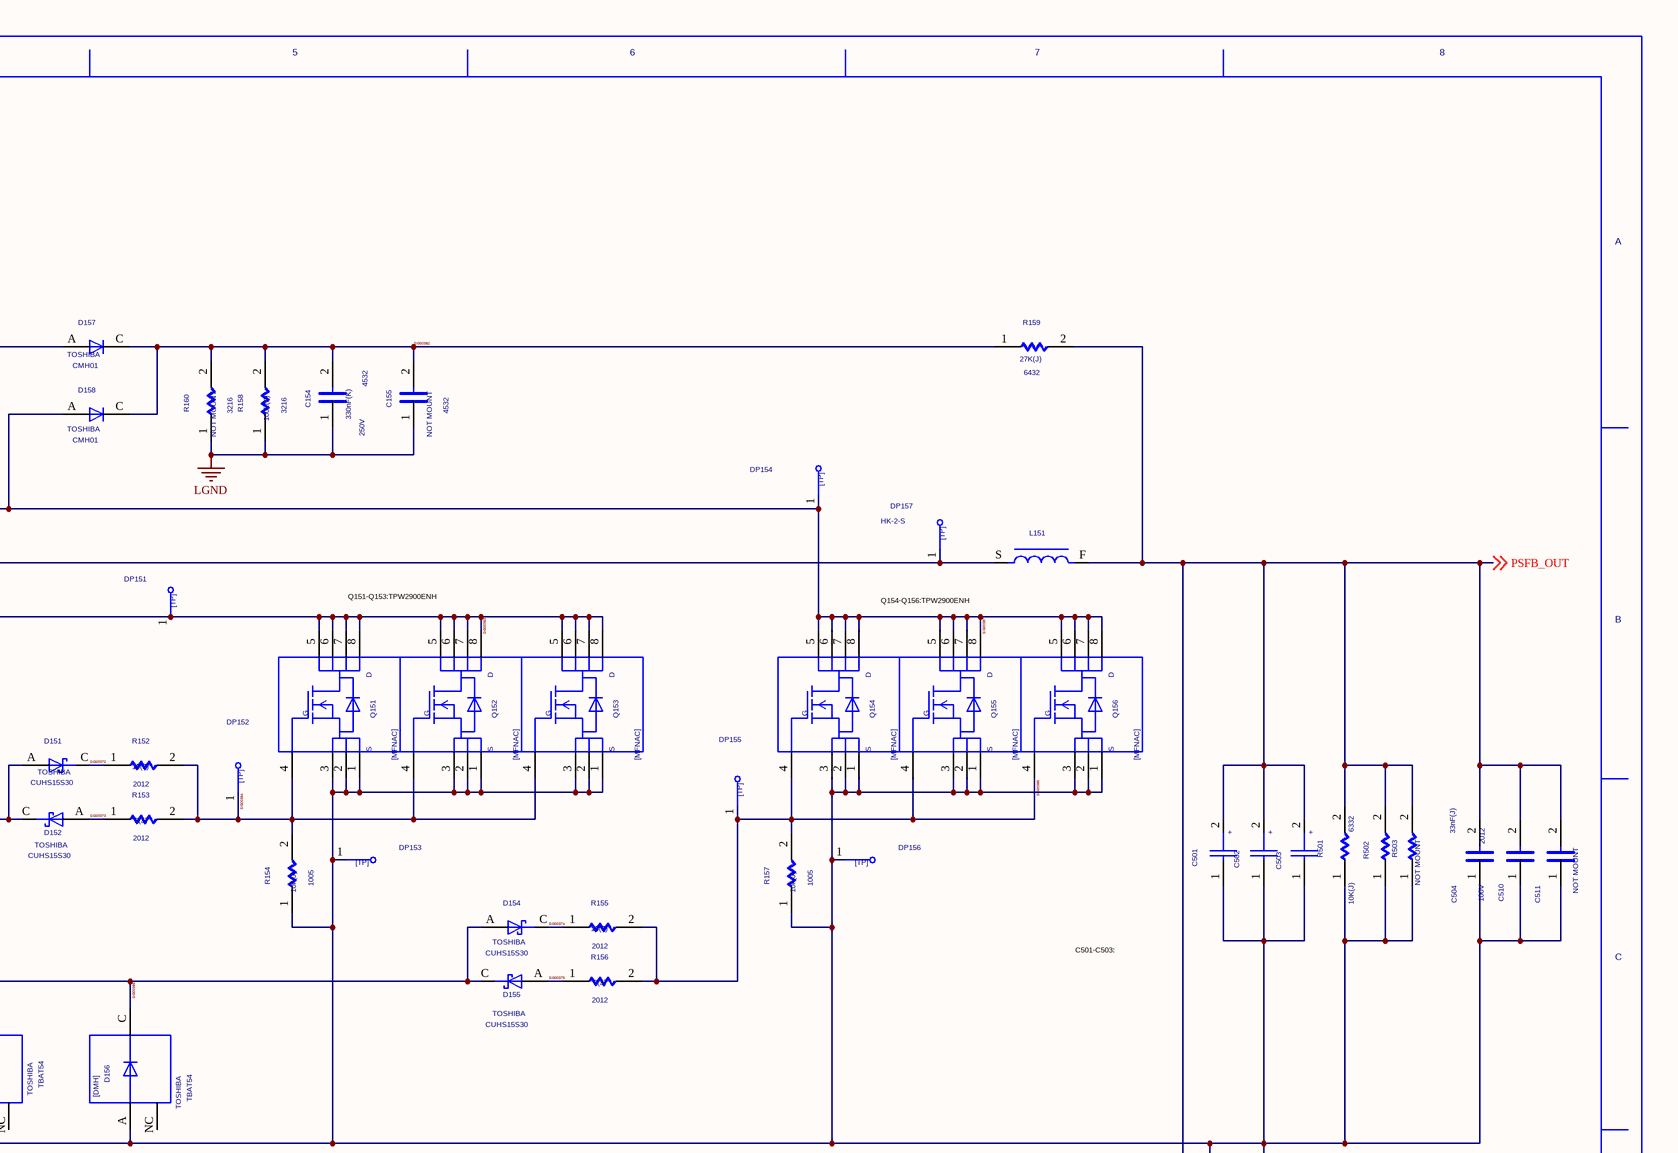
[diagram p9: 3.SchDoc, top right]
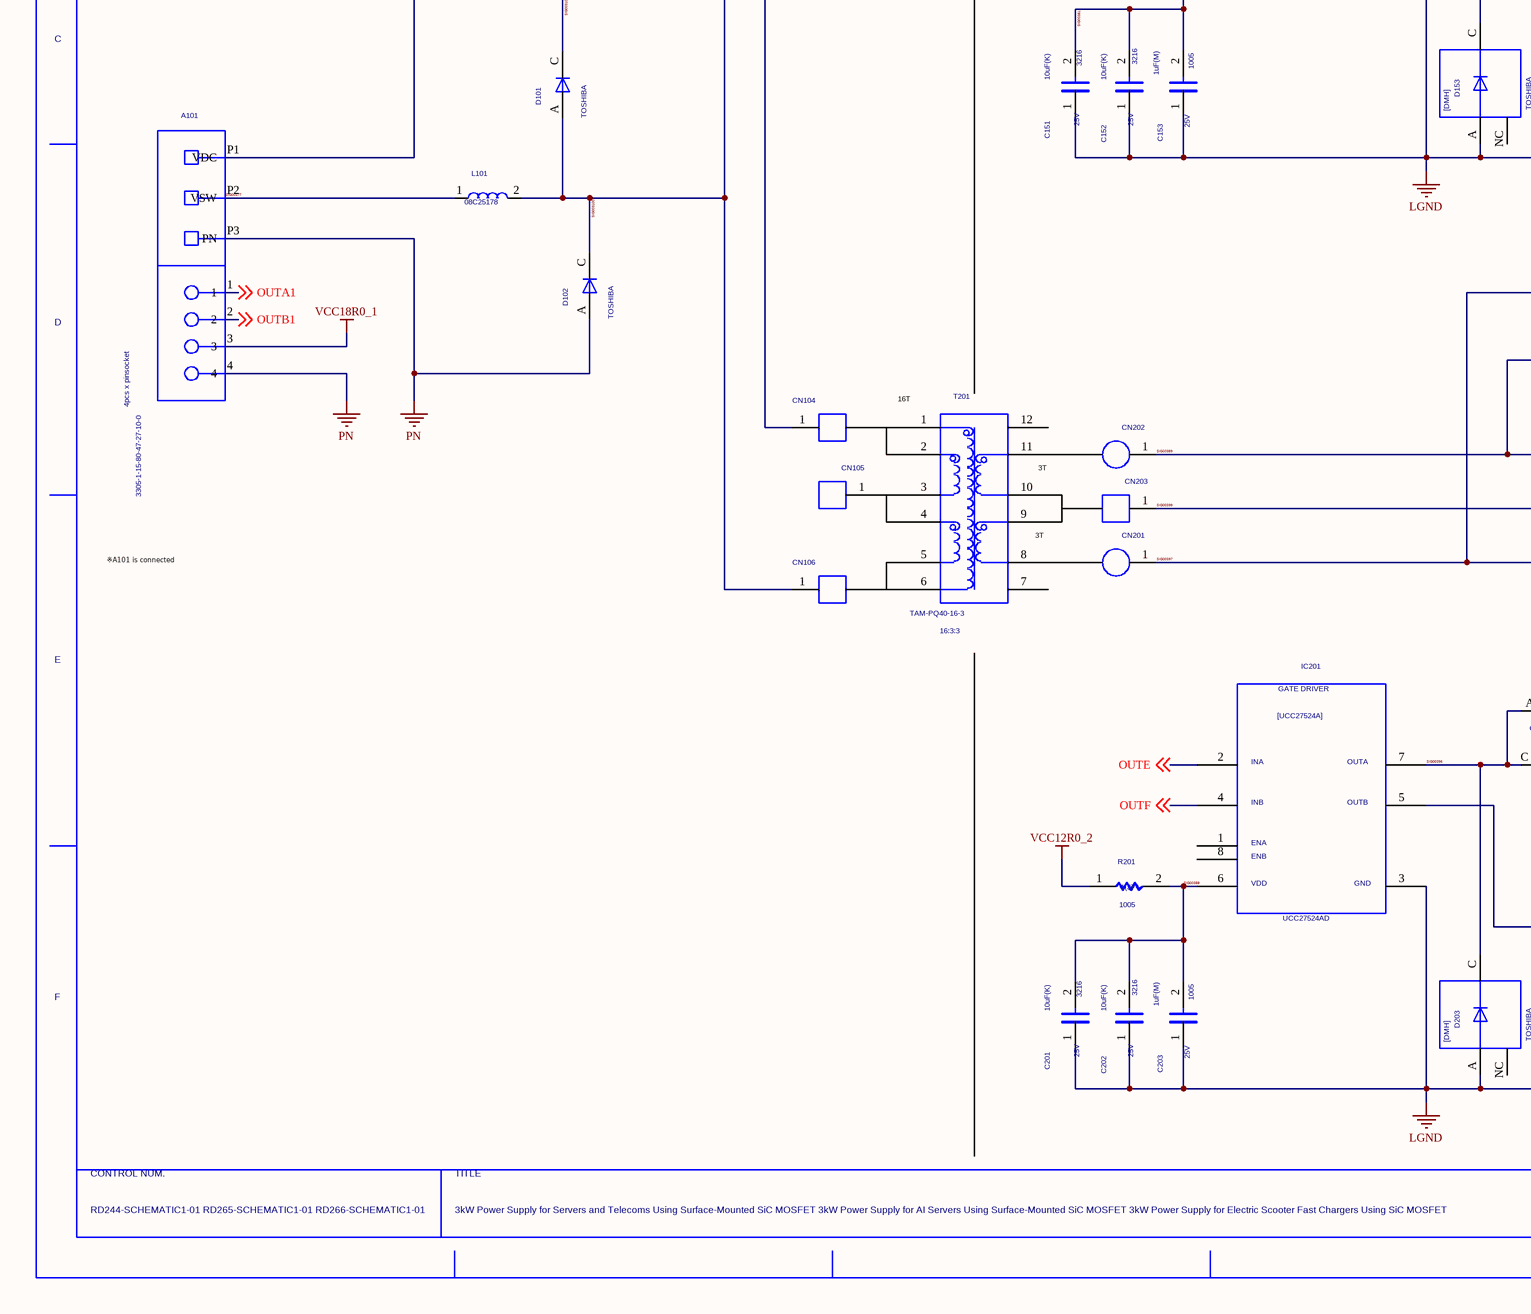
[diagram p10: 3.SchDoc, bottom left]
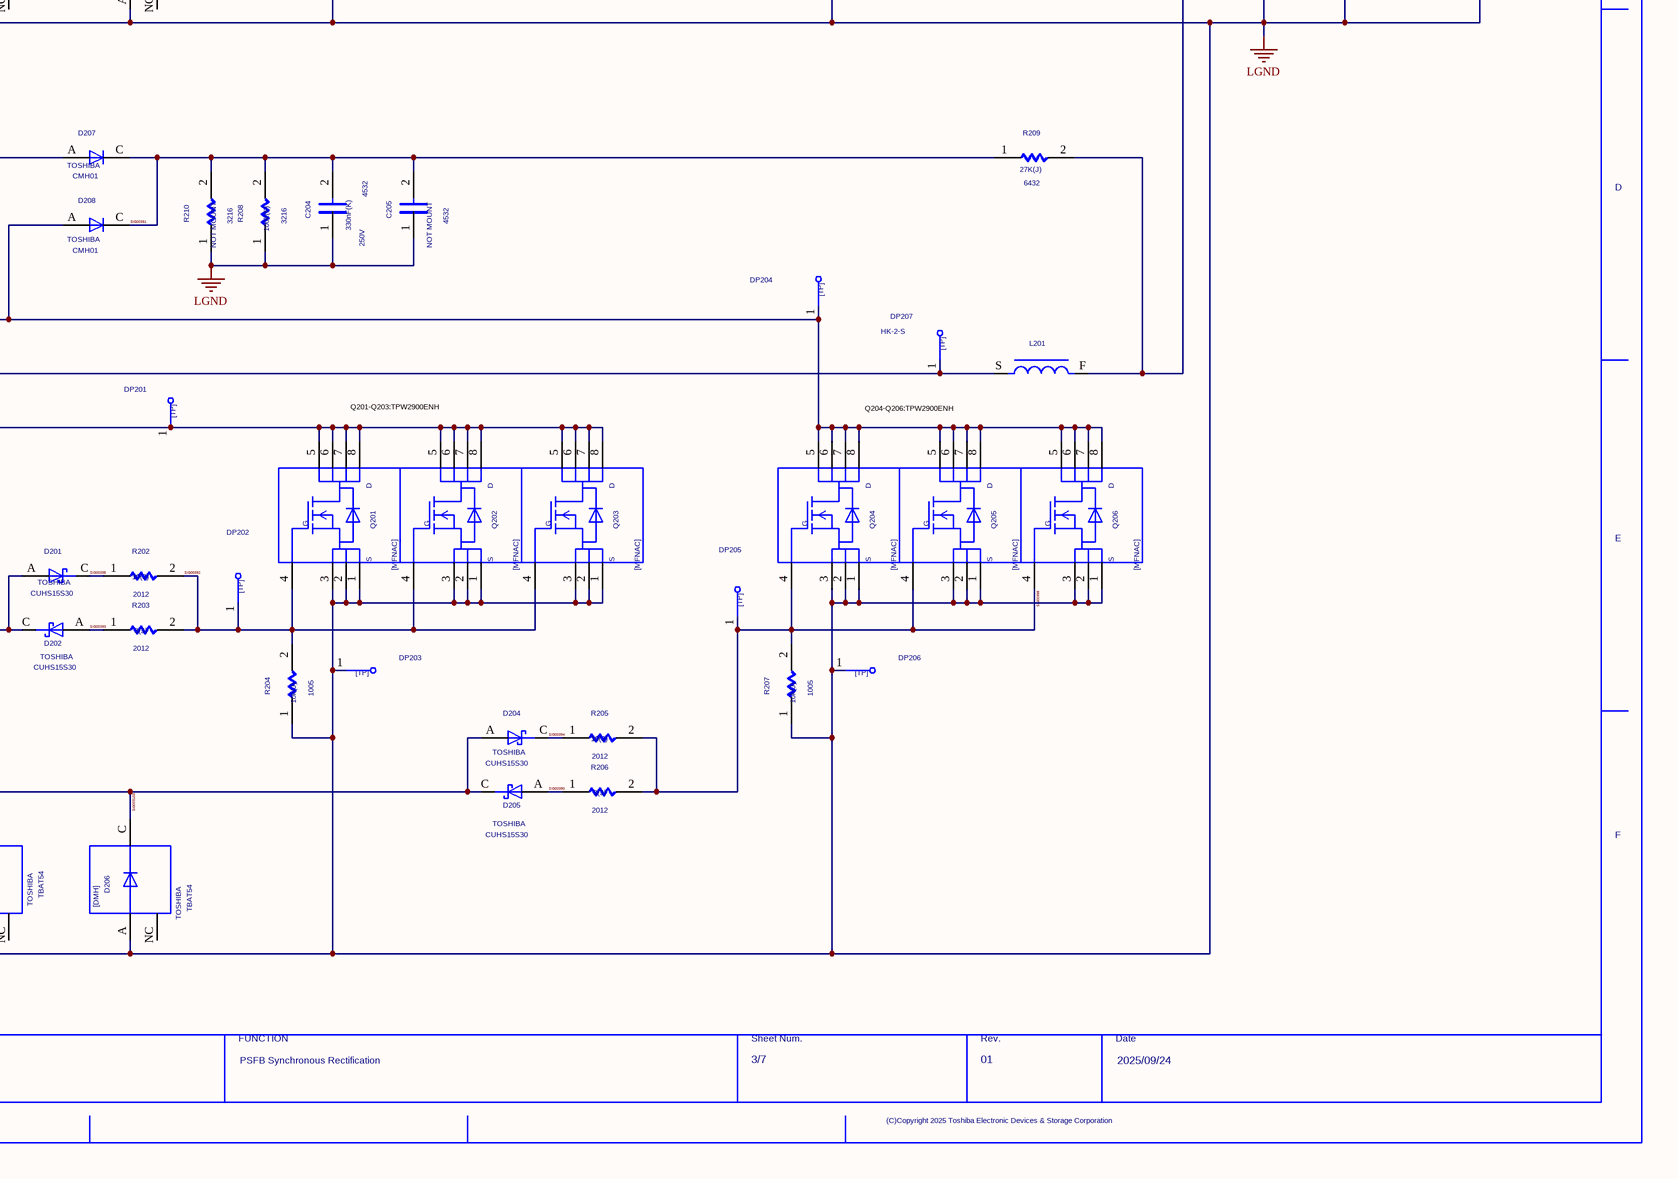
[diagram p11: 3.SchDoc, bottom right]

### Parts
(Parts that share a designator on the sheet are numbered #1, #2 ... from top to bottom, then left to right.)
A101  VAL3: 3305-1-15-80-47-27-10-0  VAL2: 4pcs x pinsocket  (hidden comment: RD-244_FB_Unit)
A102  VAL3: 3305-1-15-80-47-27-10-0  VAL2: 4pcs x pinsocket  (hidden comment: RD-244_FB_Unit)
C151  VAL1: 10uF(K)  VAL2: 25V  SIZECODESMD: 3216  (hidden comment: C)
C152  VAL1: 10uF(K)  VAL2: 25V  SIZECODESMD: 3216  (hidden comment: C)
C153  VAL1: 1uF(M)  VAL2: 25V  SIZECODESMD: 1005  (hidden comment: C)
C154  VAL1: 330nF(K)  VAL2: 250V  SIZECODESMD: 4532  (hidden comment: C)
C155  NOTMOUNT: NOT MOUNT  SIZECODESMD: 4532  (hidden comment: C)
C201  VAL1: 10uF(K)  VAL2: 25V  SIZECODESMD: 3216  (hidden comment: C)
C202  VAL1: 10uF(K)  VAL2: 25V  SIZECODESMD: 3216  (hidden comment: C)
C203  VAL1: 1uF(M)  VAL2: 25V  SIZECODESMD: 1005  (hidden comment: C)
C204  VAL1: 330nF(K)  VAL2: 250V  SIZECODESMD: 4532  (hidden comment: C)
C205  NOTMOUNT: NOT MOUNT  SIZECODESMD: 4532  (hidden comment: C)
C501  CP  (value not drawn)
C502  CP  (value not drawn)
C503  CP  (value not drawn)
C504  VAL1: 33nF(J)  VAL2: 100V  SIZECODESMD: 2012  (hidden comment: GRM21BC71E106KE01)
C510  NOTMOUNT: NOT MOUNT  (hidden comment: GRM21BC71E106KE01)
C511  GRM21BC71E106KE01  (value not drawn)
CN101  Longhole_2R5-5R5  (value not drawn)
CN102  Longhole_2R5-4R5  (value not drawn)
CN103  Longhole_2R5-5R5  (value not drawn)
CN104  Longhole_2R5-5R5  (value not drawn)
CN105  Longhole_2R5-4R5  (value not drawn)
CN106  Longhole_2R5-5R5  (value not drawn)
CN151  TH_phi_4R5  (value not drawn)
CN152  TH_phi_4R5  (value not drawn)
CN153  Longhole_4R5-8R5  (value not drawn)
CN201  TH_phi_4R5  (value not drawn)
CN202  TH_phi_4R5  (value not drawn)
CN203  Longhole_4R5-8R5  (value not drawn)
D101  USERCOMPTEXT3: TOSHIBA  (hidden comment: TRS8E65F)
D102  USERCOMPTEXT3: TOSHIBA  (hidden comment: TRS8E65F)
D151  USERCOMPTEXT3: TOSHIBA  (hidden comment: CUHS15S30)
D152  USERCOMPTEXT3: TOSHIBA  (hidden comment: CUHS15S30)
D153  USERCOMPTEXT3: TOSHIBA  VAL3: TBAT54  (hidden comment: DMH)
D154  USERCOMPTEXT3: TOSHIBA  (hidden comment: CUHS15S30)
D155  USERCOMPTEXT3: TOSHIBA  (hidden comment: CUHS15S30)
D156  USERCOMPTEXT3: TOSHIBA  VAL3: TBAT54  (hidden comment: DMH)
D157  USERCOMPTEXT3: TOSHIBA  VAL3: CMH01  (hidden comment: D)
D158  USERCOMPTEXT3: TOSHIBA  VAL3: CMH01  (hidden comment: D)
D201  USERCOMPTEXT3: TOSHIBA  (hidden comment: CUHS15S30)
D202  USERCOMPTEXT3: TOSHIBA  (hidden comment: CUHS15S30)
D203  USERCOMPTEXT3: TOSHIBA  VAL3: TBAT54  (hidden comment: DMH)
D204  USERCOMPTEXT3: TOSHIBA  (hidden comment: CUHS15S30)
D205  USERCOMPTEXT3: TOSHIBA  (hidden comment: CUHS15S30)
D206  USERCOMPTEXT3: TOSHIBA  VAL3: TBAT54  (hidden comment: DMH)
D207  USERCOMPTEXT3: TOSHIBA  VAL3: CMH01  (hidden comment: D)
D208  USERCOMPTEXT3: TOSHIBA  VAL3: CMH01  (hidden comment: D)
D251  USERCOMPTEXT3: TOSHIBA  VAL3: BAS316  (hidden comment: D)
DP151  TP  (value not drawn)
DP152  TP  (value not drawn)
DP153  TP  (value not drawn)
DP154  TP  (value not drawn)
DP155  TP  (value not drawn)
DP156  TP  (value not drawn)
DP157  VAL3: HK-2-S  (hidden comment: TP)
DP201  TP  (value not drawn)
DP202  TP  (value not drawn)
DP203  TP  (value not drawn)
DP204  TP  (value not drawn)
DP205  TP  (value not drawn)
DP206  TP  (value not drawn)
DP207  VAL3: HK-2-S  (hidden comment: TP)
IC151  VAL3: UCC27524AD  (hidden comment: L27524)
IC201  VAL3: UCC27524AD  (hidden comment: L27524)
L101  VAL3: 08C25178  (hidden comment: TMSD-Y3001)
L151  TAM-CTW32A6R5  (value not drawn)
L201  TAM-CTW32A6R5  (value not drawn)
Q151  TPH2R408QM_8PIN  (value not drawn)
Q152  TPH2R408QM_8PIN  (value not drawn)
Q153  TPH2R408QM_8PIN  (value not drawn)
Q154  TPH2R408QM_8PIN  (value not drawn)
Q155  TPH2R408QM_8PIN  (value not drawn)
Q156  TPH2R408QM_8PIN  (value not drawn)
Q201  TPH2R408QM_8PIN  (value not drawn)
Q202  TPH2R408QM_8PIN  (value not drawn)
Q203  TPH2R408QM_8PIN  (value not drawn)
Q204  TPH2R408QM_8PIN  (value not drawn)
Q205  TPH2R408QM_8PIN  (value not drawn)
Q206  TPH2R408QM_8PIN  (value not drawn)
R101  USERCOMPTEXT1: 300K(J)  USERCOMPTEXT2: 1W  SIZECODESMD: 6332  (hidden comment: R)
R102  USERCOMPTEXT1: 300K(J)  USERCOMPTEXT2: 1W  SIZECODESMD: 6332  (hidden comment: R)
R151  VAL1: 1(J)  SIZECODESMD: 1005  (hidden comment: R)
R152  VAL1: 10(J)  SIZECODESMD: 2012  (hidden comment: R)
R153  VAL1: 3(J)  SIZECODESMD: 2012  (hidden comment: R)
R154  VAL1: 10k(J)  SIZECODESMD: 1005  (hidden comment: R)
R155  VAL1: 10(J)  SIZECODESMD: 2012  (hidden comment: R)
R156  VAL1: 3(J)  SIZECODESMD: 2012  (hidden comment: R)
R157  VAL1: 10k(J)  SIZECODESMD: 1005  (hidden comment: R)
R158  VAL1: 100k(F)  SIZECODESMD: 3216  (hidden comment: R)
R159  USERCOMPTEXT1: 27K(J)  SIZECODESMD: 6432  (hidden comment: R)
R160  NOTMOUNT: NOT MOUNT  SIZECODESMD: 3216  (hidden comment: R)
R201  VAL1: 1(J)  SIZECODESMD: 1005  (hidden comment: R)
R202  VAL1: 10(J)  SIZECODESMD: 2012  (hidden comment: R)
R203  VAL1: 3(J)  SIZECODESMD: 2012  (hidden comment: R)
R204  VAL1: 10k(J)  SIZECODESMD: 1005  (hidden comment: R)
R205  VAL1: 10(J)  SIZECODESMD: 2012  (hidden comment: R)
R206  VAL1: 3(J)  SIZECODESMD: 2012  (hidden comment: R)
R207  VAL1: 10k(J)  SIZECODESMD: 1005  (hidden comment: R)
R208  VAL1: 100k(F)  SIZECODESMD: 3216  (hidden comment: R)
R209  USERCOMPTEXT1: 27K(J)  SIZECODESMD: 6432  (hidden comment: R)
R210  NOTMOUNT: NOT MOUNT  SIZECODESMD: 3216  (hidden comment: R)
R251  VAL1: 330(J)  SIZECODESMD: 3216  (hidden comment: R)
R501  USERCOMPTEXT1: 10K(J)  SIZECODESMD: 6332  (hidden comment: R)
R502  R  (value not drawn)
R503  NOTMOUNT: NOT MOUNT  (hidden comment: R)
T101  VAL1: 1:100  VAL3: PE-63587  (hidden comment: T2AA)
T151  VAL3: TAM-PQ40-16-3  USERCOMPTEXT1: 16:3:3  (hidden comment: T3_12V67A)
T201  VAL3: TAM-PQ40-16-3  USERCOMPTEXT1: 16:3:3  (hidden comment: T3_12V67A)
U?#3  DATE: 2025/09/24  DRAWINGNUMBER: RD244-SCHEMATIC1-01 / RD265-SCHEMATIC1-01 / RD266-SCHEMATIC1-01  TITLE: 3kW Power Supply for Servers and Telecoms Using Surface-Mounted SiC MOSFET / 3kW Power Supply for AI Servers Using Surface-Mounted SiC MOSFET / 3kW Power Supply for Electric Scooter Fast Chargers Using SiC MOSFET  FUNCTION: PSFB Synchronous Rectification  SHEETNUMBER: 3/7  REVISION: 01  (hidden comment: WAKU_DEF_A3_1)

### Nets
LGND: C151.1 C152.1 C153.1 C154.1 C155.1 C201.1 C202.1 C203.1 C204.1 C205.1 C501.1 C502.1 C503.1 C504.1 C510.1 C511.1 D153.A D156.A D203.A D206.A DP153.1 DP156.1 DP203.1 DP206.1 IC151.3 IC201.3 Q151.1 Q151.2 Q151.3 Q152.1 Q152.2 Q152.3 Q153.1 Q153.2 Q153.3 Q154.1 Q154.2 Q154.3 Q155.1 Q155.2 Q155.3 Q156.1 Q156.2 Q156.3 Q201.1 Q201.2 Q201.3 Q202.1 Q202.2 Q202.3 Q203.1 Q203.2 Q203.3 Q204.1 Q204.2 Q204.3 Q205.1 Q205.2 Q205.3 Q206.1 Q206.2 Q206.3 R154.1 R157.1 R158.1 R160.1 R204.1 R207.1 R208.1 R210.1 R251.1 R501.1 R502.1 R503.1 T101.3
PN: A101.4 A101.P3(PN) A102.4 A102.P3(PN) D102.A R102.1
VCC12R0_2: R151.1 R201.1
VCC18R0_1: A101.3 A102.3
CS: D251.C ; off-sheet CS
OUTA1: A101.1 ; off-sheet OUTA1
OUTB1: A101.2 ; off-sheet OUTB1
OUTC1: A102.1 ; off-sheet OUTC1
OUTD1: A102.2 ; off-sheet OUTD1
OUTE: IC151.2 IC201.2 ; off-sheet OUTE
OUTF: IC151.4 IC201.4 ; off-sheet OUTF
PFC_OUT: R101.2 T101.2 ; off-sheet PFC_OUT
PSFB_OUT: C501.2 C502.2 C503.2 C504.2 C510.2 C511.2 L151.F L201.F R159.2 R209.2 R501.2 R502.2 R503.2 ; off-sheet PSFB_OUT
SIG00372: D151.C R152.1
SIG00373: D152.A R153.1
SIG00374: D154.C R155.1
SIG00375: D155.A R156.1
SIG00376: CN153.1 DP157.1 L151.S
SIG00377: A101.P2(VSW) L101.1
SIG00378: D251.A R251.2 T101.5
SIG00379: R101.1 R102.2
SIG00380: D151.A D152.C D153.C IC151.7
SIG00381: C151.2 C152.2 C153.2 IC151.6 R151.2
SIG00382: C154.2 C155.2 D157.C D158.C R158.2 R159.1 R160.2
SIG00383: CN151.1 D157.A DP151.1 Q151.5 Q151.6 Q151.7 Q151.8 Q152.5 Q152.6 Q152.7 Q152.8 Q153.5 Q153.6 Q153.7 Q153.8
SIG00384: DP152.1 Q151.4 Q152.4 Q153.4 R152.2 R153.2 R154.2
SIG00385: D154.A D155.C D156.C IC151.5
SIG00386: DP155.1 Q154.4 Q155.4 Q156.4 R155.2 R156.2 R157.2
SIG00387: CN152.1 D158.A DP154.1 Q154.5 Q154.6 Q154.7 Q154.8 Q155.5 Q155.6 Q155.7 Q155.8 Q156.5 Q156.6 Q156.7 Q156.8
SIG00388: C201.2 C202.2 C203.2 IC201.6 R201.2
SIG00389: CN202.1 D208.A DP204.1 Q204.5 Q204.6 Q204.7 Q204.8 Q205.5 Q205.6 Q205.7 Q205.8 Q206.5 Q206.6 Q206.7 Q206.8
SIG00390: D205.A R206.1
SIG00391: C204.2 C205.2 D207.C D208.C R208.2 R209.1 R210.2
SIG00392: DP202.1 Q201.4 Q202.4 Q203.4 R202.2 R203.2 R204.2
SIG00393: D202.A R203.1
SIG00394: D204.C R205.1
SIG00395: D201.C R202.1
SIG00396: D201.A D202.C D203.C IC201.7
SIG00397: CN201.1 D207.A DP201.1 Q201.5 Q201.6 Q201.7 Q201.8 Q202.5 Q202.6 Q202.7 Q202.8 Q203.5 Q203.6 Q203.7 Q203.8
SIG00398: DP205.1 Q204.4 Q205.4 Q206.4 R205.2 R206.2 R207.2
SIG00399: CN203.1 DP207.1 L201.S
SIG003100: CN103.1 CN106.1 D101.A D102.C L101.2
SIG003101: A102.P2(VSW) CN101.1 CN104.1
SIG003102: A101.P1(VDC) A102.P1(VDC) D101.C T101.1
SIG003103: D204.A D205.C D206.C IC201.5

Not connected (* = marked no-connect by the designer): CN102 1; CN105 1; D153 NC; D156 NC; D203 NC; D206 NC; IC151 1 8; IC201 1 8; T101 4 6 7; T151 1 2 3 4 5 6 7 8 9 10 11 12; T201 1 2 3 4 5 6 7 8 9 10 11 12

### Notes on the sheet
- Primary
- Secondary
- (near T151) 16T
- (near T151) 3T
- Q151-Q153:TPW2900ENH
- Q154-Q156:TPW2900ENH
- ※A102 is connected
  to CN701 and CN702 of RD244-SCHEMATICS3
- C501-C503:
- (near T201) 16T
- (near T201) 3T
- ※A101 is connected
  to CN701 and CN702 of RD244-SCHEMATICS3
- Q201-Q203:TPW2900ENH
- Q204-Q206:TPW2900ENH

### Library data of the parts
A101 A102 = RD-244_FB_UNIT: TIME: 11:34:46; UPDATEUSER: t4887876; UPDATETIME: 08:09:20; SAVECOUNT: 38; SAVEAREA0: -20981,-344,43891,33349; OriginalSymbolOrigin: (0,50800)
C151 C152 C201 C202 = C_Dup2: OriginalSymbolOrigin: (2540,7620); COMP: PRT_46; MAXGCOUNT: 1; SAVECOUNT: 0
C153 C203 = C_Dup2: as C11 on sheet 1
C154 C204 = C: SQ_PART_MODEL: CON_150N; OriginalSymbolOrigin: (2540,7620); GATENO: 1; ADSCNVFLAG: ON; ADSCOMPONENTNAME: C_4532; COMP: K0301583; CHIPSIZE: 1005; SAVECOUNT: 0
C155 C205 = C: SQ_PART_MODEL: CON_150N; VAL1: 330nF(K); VAL2: 250V; OriginalSymbolOrigin: (2540,7620); GATENO: 1; ADSCNVFLAG: ON; ADSCOMPONENTNAME: C_4532; COMP: K0301583; CHIPSIZE: 1005; SAVECOUNT: 0
C501-C503 = CP: SAVEAREA0: -1450,-153,20294,13055; SAVECOUNT: 52; TIME: 15:02:55; UPDATEUSER: fukuda-y; UPDATETIME: 16:13:42; VAL1: 330uF(M); VAL2: 63V; OriginalSymbolOrigin: (2540,10160); COMP: PRT_3; CHIPSIZE: D10xL22; MAXGCOUNT: 1; SIZECODESMD: DIP
C504 = GRM21BC71E106KE01: as C69 on sheet 2
C510 = GRM21BC71E106KE01: TIME: 10:25:11; UPDATEUSER: t4887876; UPDATETIME: 16:23:00; SAVECOUNT: 11; VAL1: 33nF(J); VAL2: 100V; MAKER: Murata; CHIPSET: 2012; OriginalSymbolOrigin: (2540,7620); CHIPSIZE: 1005; MAXGCOUNT: 1
C511 = GRM21BC71E106KE01: TIME: 10:25:11; UPDATEUSER: t4887876; UPDATETIME: 16:23:00; SAVECOUNT: 11; VAL1: 33nF(J); VAL2: 100V; MAKER: Murata; CHIPSET: 2012; NOTMOUNT: NOT MOUNT; OriginalSymbolOrigin: (2540,7620); CHIPSIZE: 1005; MAXGCOUNT: 1
CN101 CN103 CN104 CN106 = LONGHOLE_2R5-5R5: TIME: 17:17:39; UPDATEUSER: t4887876; UPDATETIME: 09:28:53; SAVECOUNT: 11; VAL3: PCB Pad; OriginalSymbolOrigin: (5080,5080)
CN102 CN105 = LONGHOLE_2R5-4R5: TIME: 17:17:39; UPDATEUSER: t4887876; UPDATETIME: 09:28:53; SAVECOUNT: 11; VAL3: PCB Pad; OriginalSymbolOrigin: (5080,5080)
CN151 CN152 CN201 CN202 = TH_PHI_4R5: TIME: 17:17:39; UPDATEUSER: t4887876; UPDATETIME: 10:35:58; SAVECOUNT: 11; VAL3: PCB Pad; OriginalSymbolOrigin: (5080,5080)
CN153 CN203 = LONGHOLE_4R5-8R5: TIME: 17:17:39; UPDATEUSER: t4887876; UPDATETIME: 09:28:53; SAVECOUNT: 12; VAL3: PCB Pad; OriginalSymbolOrigin: (5080,5080)
D101 D102 = TRS8E65F: SAVEAREA0: -225,-91,12804,7836; SAVECOUNT: 5; TIME: 14:49:55; UPDATEUSER: t6860224; UPDATETIME: 17:57:03; VAL3: TRS8E65H; OriginalSymbolOrigin: (5080,5080); VAL2: 650V,8A; MAXGCOUNT: 1
D151 D152 D154 D155 D201 D202 D204 D205 = CUHS15S30: SAVEAREA0: -4630,-153,17114,13055; TIME: 14:49:55; UPDATEUSER: t4887876; UPDATETIME: 17:19:09; SAVECOUNT: 10; OriginalSymbolOrigin: (5080,5080); USERCOMPTEXT2: 30V,1.5A
D153 D156 D203 D206 = DMH: SAVEAREA0: -4931,-287,27399,20979; TIME: 08:58:08; UPDATEUSER: kishi-s; UPDATETIME: 09:01:52; SAVECOUNT: 2; OriginalSymbolOrigin: (5080,17780); USERCOMPTEXT2: 30V,0.2A; COMP: PRT_25
D157 D158 D207 D208 = D_Dup1: SAVEAREA0: -225,-91,12804,7836; SAVECOUNT: 3; TIME: 14:49:55; UPDATEUSER: 19870035; UPDATETIME: 14:20:16; OriginalSymbolOrigin: (5080,5080); USERCOMPTEXT2: 200V,3A; COMP: PRT_14; MAXGCOUNT: 1
D251 = D_Dup1: SAVEAREA0: -225,-91,12804,7836; SAVECOUNT: 3; TIME: 14:49:55; UPDATEUSER: 19870035; UPDATETIME: 14:20:16; OriginalSymbolOrigin: (5080,5080); USERCOMPTEXT2: 80V,0.1A; COMP: PRT_27; MAXGCOUNT: 1
DP151-DP156 DP201-DP206 = TP: as DP51 on sheet 2
DP157 DP207 = TP: as DP56 on sheet 2
IC151 IC201 = L27524: SAVEAREA0: -24347,-591,50370,48694; SAVECOUNT: 22; TIME: 15:02:55; UPDATEUSER: cae; UPDATETIME: 14:54:38; OriginalSymbolOrigin: (7620,45720); COMP: PRT_63
L101 = TMSD-Y3001: VAL1: 13uH; TIME: 11:29:15; UPDATEUSER: t4887876; UPDATETIME: 13:47:51; SAVECOUNT: 2; VAL2: (Rated Current/Idc=0A); OriginalSymbolOrigin: (2540,5080)
L151 L201 = TAM-CTW32A6R5: SAVECOUNT: 8; SAVEAREA0: -384,-828,17939,11225; TIME: 16:55:46; UPDATEUSER: t4887876; UPDATETIME: 06:59:32; VAL1: 9.5uH; VAL2: 32A; MAKER: TAMURA; OriginalSymbolOrigin: (2540,5080); MAXGCOUNT: 1
Q151 Q152 Q154 Q201 Q202 Q204 = TPH2R408QM_8PIN: TIME: 18:29:30; UPDATEUSER: t4887876; UPDATETIME: 15:52:00; SAVECOUNT: 28; SAVEAREA0: -10143,-336,37609,28718; COMP: TPW2900ENH; VAL2: 120A; OriginalSymbolOrigin: (5080,25400); MAXGCOUNT: 1; USERCOMPTEXT3: TOSHIBA
Q153 Q156 Q203 Q206 = TPH2R408QM_8PIN: TIME: 18:29:30; UPDATEUSER: t4887876; UPDATETIME: 15:52:00; SAVECOUNT: 28; SAVEAREA0: -10143,-336,37609,28718; COMP: TPW2900ENH; VAL2: 120A; NOTMOUNT: MOUNT; OriginalSymbolOrigin: (5080,25400); MAXGCOUNT: 1; USERCOMPTEXT3: TOSHIBA
Q155 Q205 = TPH2R408QM_8PIN: TIME: 18:29:30; UPDATEUSER: t4887876; UPDATETIME: 15:52:00; SAVECOUNT: 28; SAVEAREA0: -10143,-336,37609,28718; COMP: TPW2900ENH; VAL1: 80V; VAL2: 120A; OriginalSymbolOrigin: (5080,25400); MAXGCOUNT: 1; USERCOMPTEXT3: TOSHIBA
R101 R102 = R_Dup1: SQ_PART_MODEL: RES_47K; NOTMOUNT: MOUNT; VAL1: 47k(J); OriginalSymbolOrigin: (5080,5080); MAXGCOUNT: 1; ADSCNVFLAG: ON; ADSCOMPONENTNAME: R_6332; COMP: GDM010001640; CHIPSIZE: 6432; SAVECOUNT: 0
R151 R154 R157 R201 R204 R207 = R_Dup2: as R52 on sheet 2
R152 R153 R155 R156 R202 R203 R205 R206 = R_Dup2: VAL2: 250mW; OriginalSymbolOrigin: (5080,5080); COMP: R2012; CHIPSIZE: 3216; MAXGCOUNT: 1; SAVECOUNT: 0
R158 R208 = R_Dup2: VAL2: 250mW; OriginalSymbolOrigin: (5080,5080); COMP: PRT_5; MAXGCOUNT: 1; ADSCOMPONENTNAME: R_3216; SAVECOUNT: 0
R159 R209 = R_Dup1: SQ_PART_MODEL: RES_47K; VAL2: 1W; VAL1: 47k(J); OriginalSymbolOrigin: (5080,5080); ADSCNVFLAG: ON; COMP: CRGH2512J620R; MAXGCOUNT: 1; SAVECOUNT: 0
R160 R210 = R_Dup2: VAL2: 250mW; VAL1: 100k(F); OriginalSymbolOrigin: (5080,5080); COMP: PRT_5; MAXGCOUNT: 1; ADSCOMPONENTNAME: R_3216; SAVECOUNT: 0
R251 = R_Dup2: SQ_PART_MODEL: RES_4.87K; VAL2: 250mW; OriginalSymbolOrigin: (5080,5080); COMP: PRT_5; CHIPSIZE: 1608; MAXGCOUNT: 1; ADSCNVFLAG: ON; ADSCOMPONENTNAME: R_3216; SAVECOUNT: 0
R501 = R_Dup1: SQ_PART_MODEL: RES_47K; VAL2: 1W; VAL1: 47k(J); OriginalSymbolOrigin: (5080,5080); ADSCNVFLAG: ON; ADSCOMPONENTNAME: R_6332; COMP: GDM010001640; CHIPSIZE: 6432; MAXGCOUNT: 1; SAVECOUNT: 0
R502 = R_Dup1: SQ_PART_MODEL: RES_47K; NOTMOUNT: NOT MOUNT; VAL2: 1W; VAL1: 47k(J); OriginalSymbolOrigin: (5080,5080); USERCOMPTEXT1: 10K(J); ADSCNVFLAG: ON; ADSCOMPONENTNAME: R_6332; SIZECODESMD: 6332; COMP: GDM010001640; CHIPSIZE: 6432; MAXGCOUNT: 1; SAVECOUNT: 0
R503 = R_Dup1: SQ_PART_MODEL: RES_47K; VAL2: 1W; VAL1: 47k(J); OriginalSymbolOrigin: (5080,5080); USERCOMPTEXT1: 10K(J); ADSCNVFLAG: ON; ADSCOMPONENTNAME: R_6332; SIZECODESMD: 6332; COMP: GDM010001640; CHIPSIZE: 6432; MAXGCOUNT: 1; SAVECOUNT: 0
T101 = T2AA: TIME: 11:34:46; UPDATEUSER: t4887876; UPDATETIME: 16:34:34; SAVECOUNT: 11; SAVEAREA0: -20981,-344,43891,33349; OriginalSymbolOrigin: (5080,30480); COMP: PRT_65; MAXGCOUNT: 1
T151 T201 = TAM-PQ40-20-3: UPDATEUSER: t4887876; UPDATETIME: 20:17:22; SAVECOUNT: 21; TIME: 16:40:06; SAVEAREA0: -9901,-21944,29587,7006; ORIGINALSYMBOLORIGIN: (0,0)
U?#3 = WAKU_DEF_A3_1: PLOTTIME: HH:MM; SAVEAREA0: 96913,-567914,509243,-368858; TIME: 12:01:09; UPDATEUSER: t5459927; UPDATETIME: 13:12:48; SAVECOUNT: 3; ZONEOFFSETX: 36; ZONEOFFSETY: -24; OriginalSymbolOrigin: (12700,-12700); SHTSAVECOUNT: 272; DESIGNED: TOSHIBA

## Sheet 4.SchDoc
size 612 x 444 mm
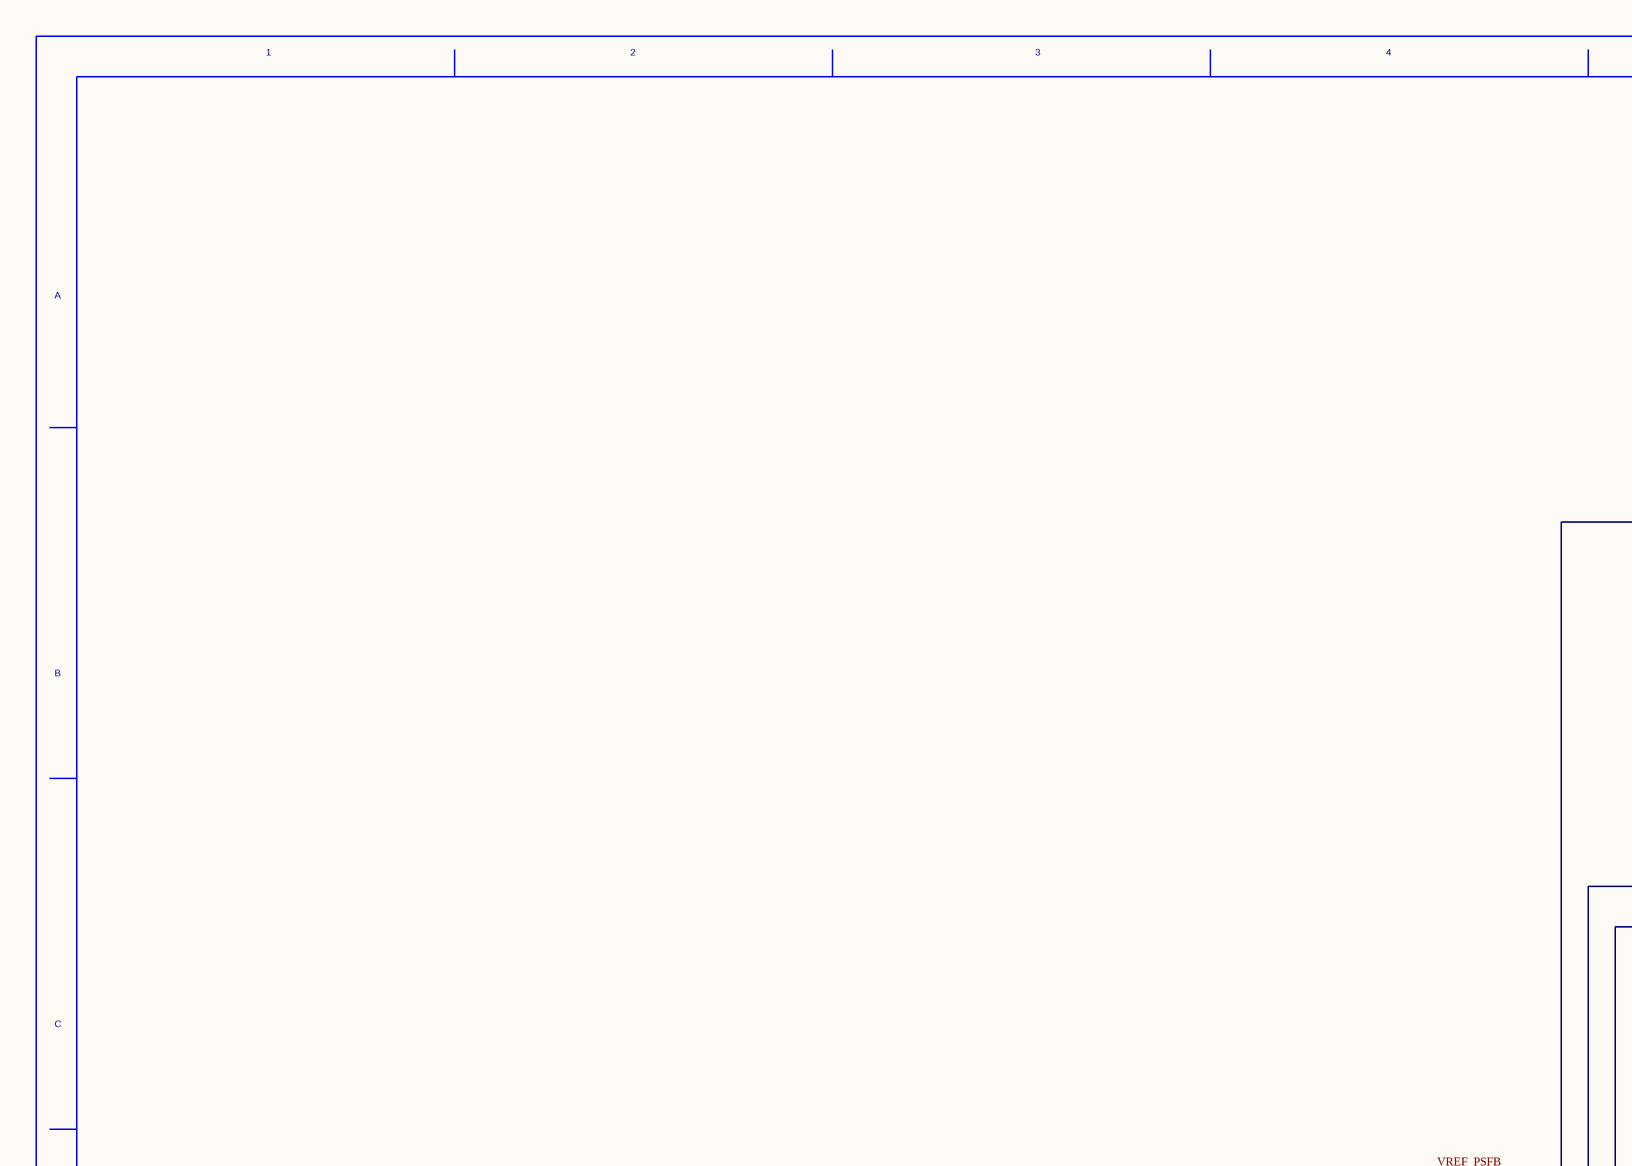
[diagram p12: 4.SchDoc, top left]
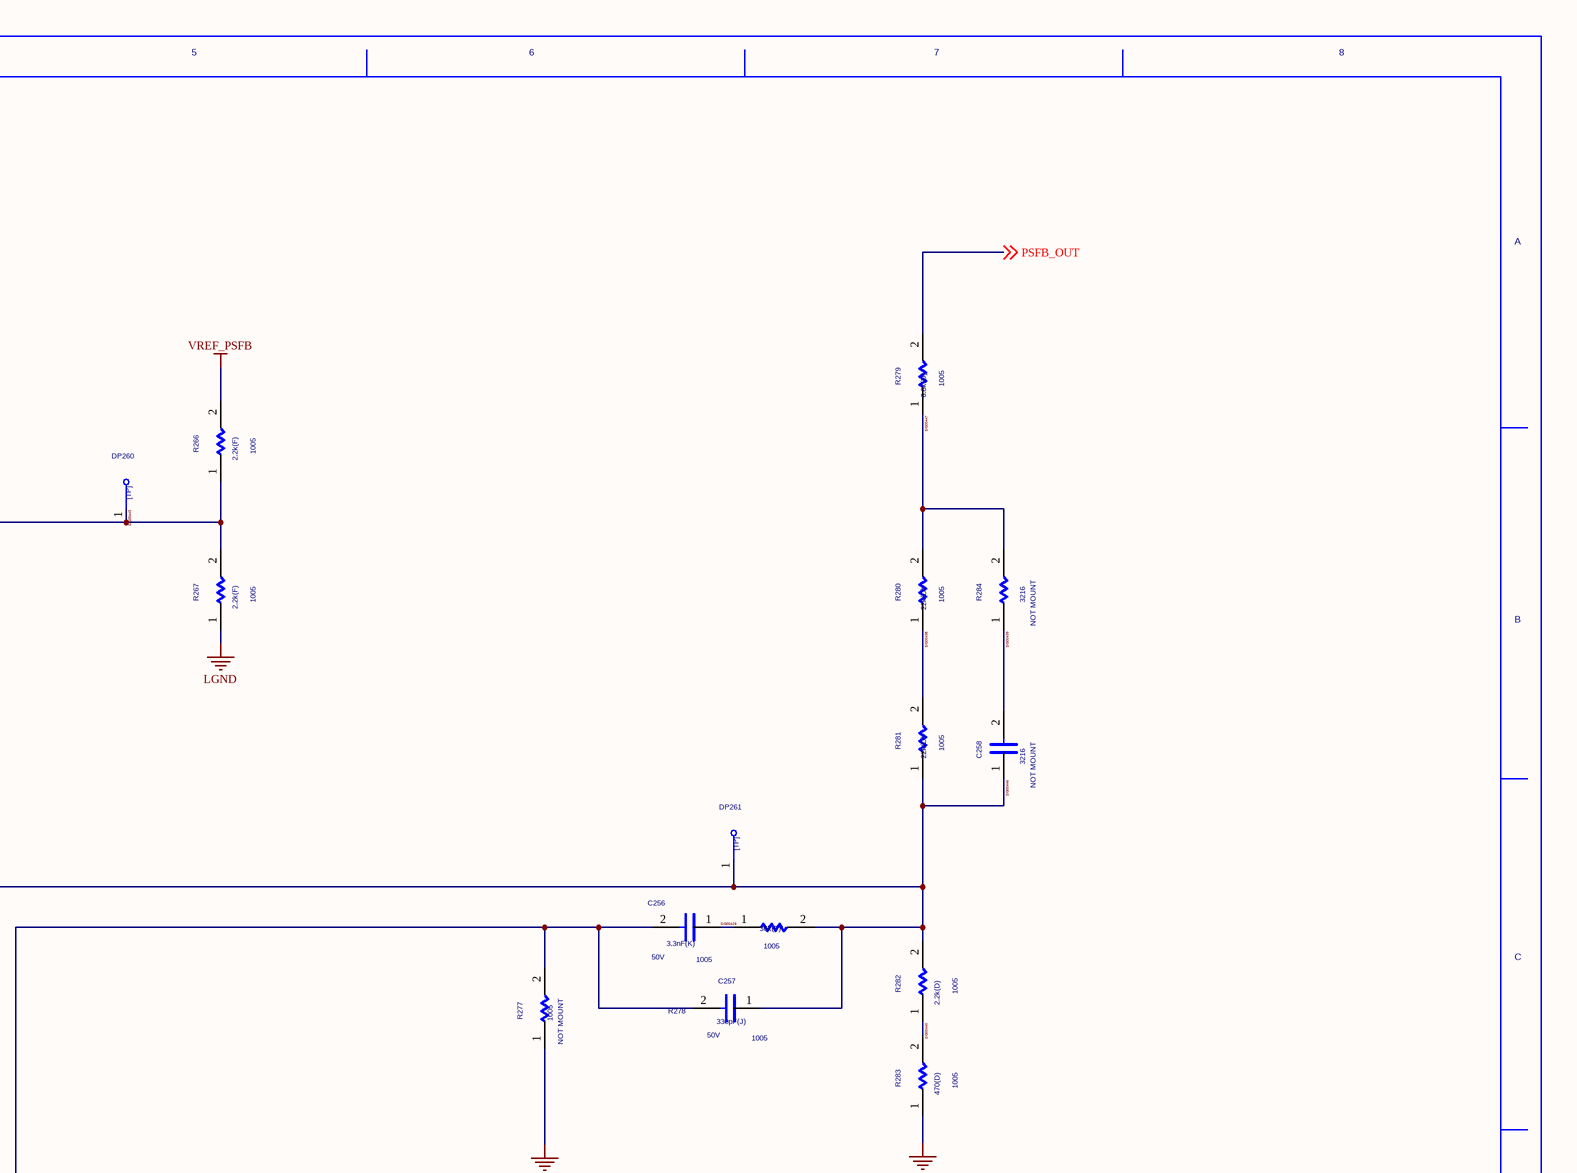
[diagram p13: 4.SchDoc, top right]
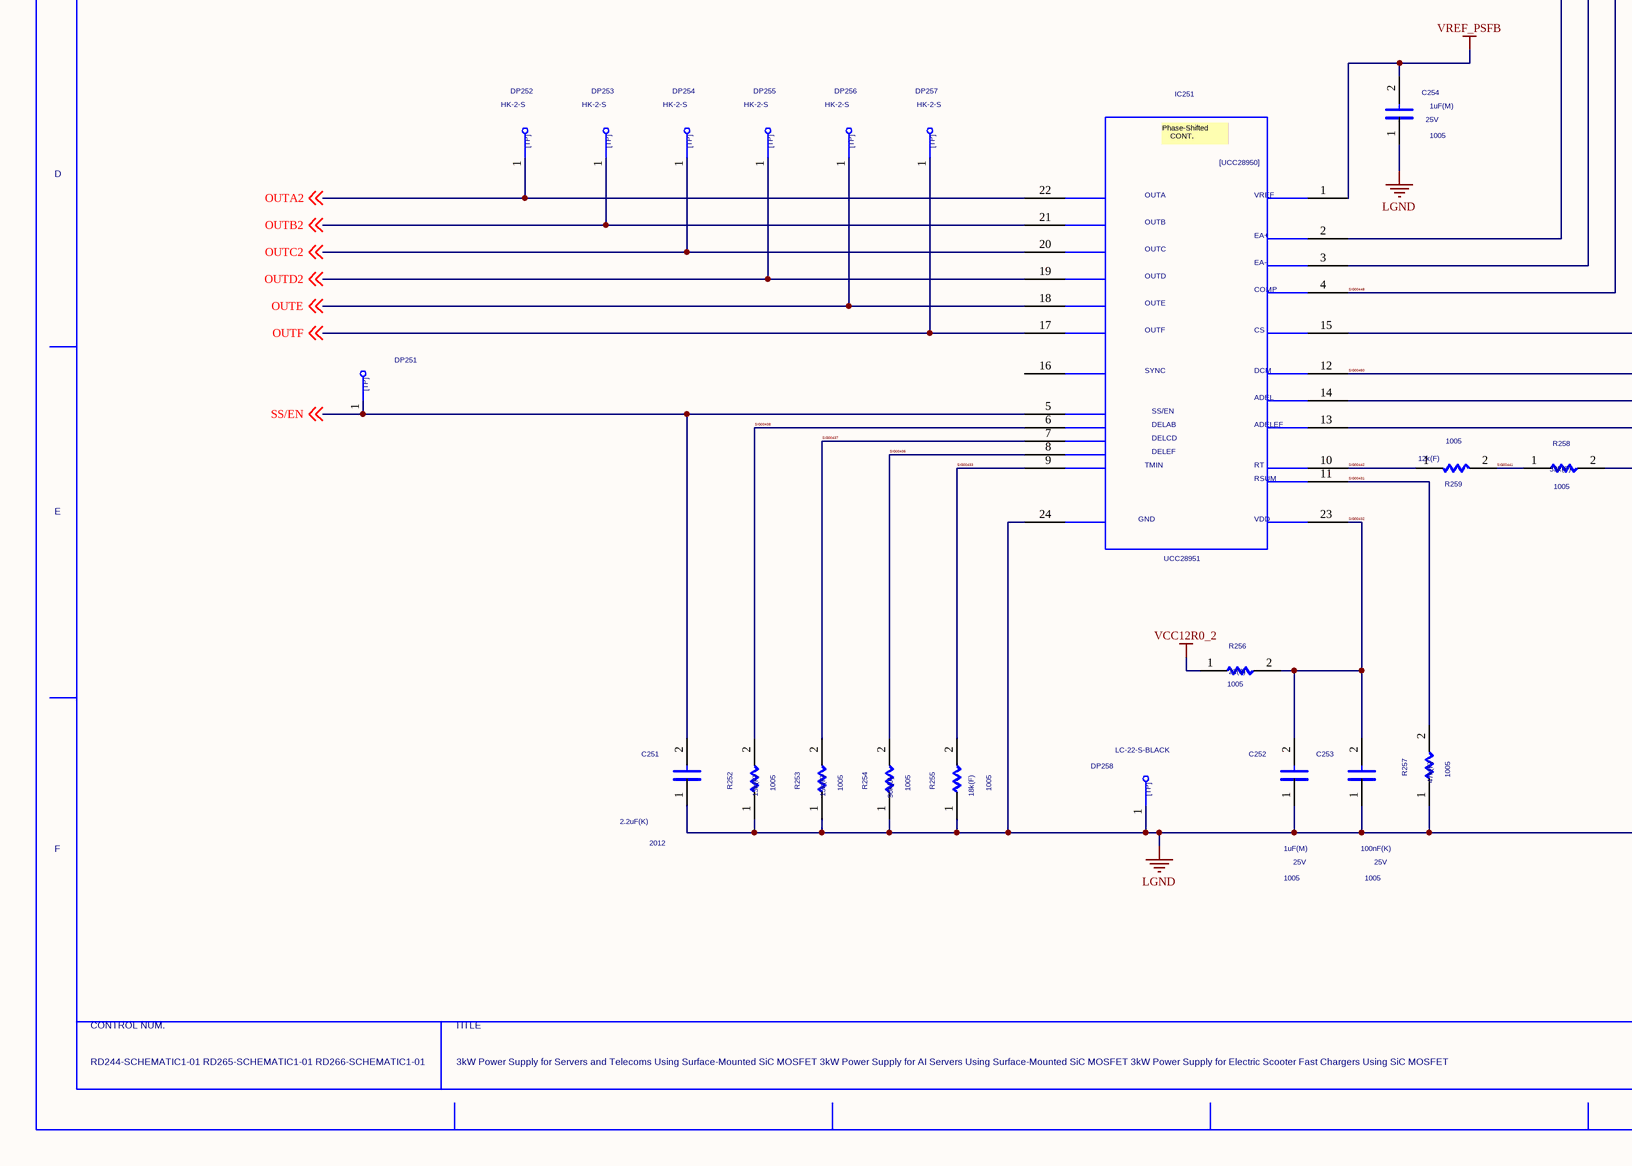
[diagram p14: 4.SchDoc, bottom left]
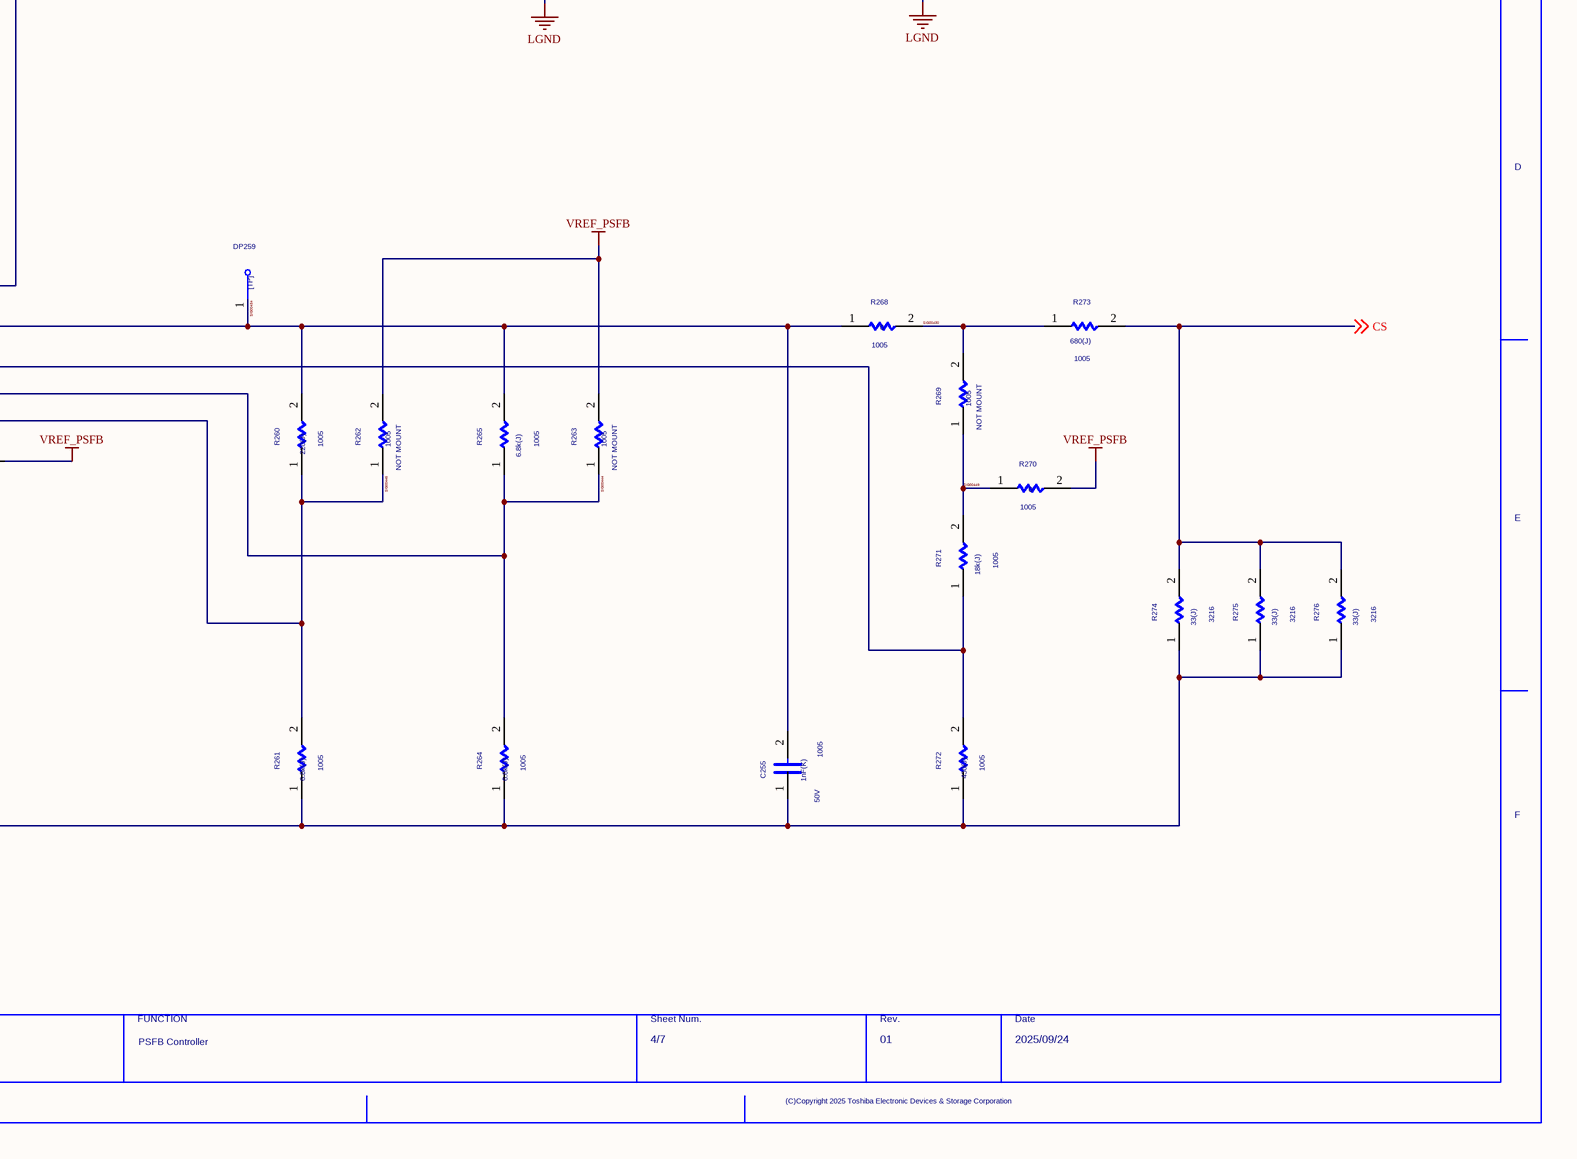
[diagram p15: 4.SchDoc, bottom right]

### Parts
(Parts that share a designator on the sheet are numbered #1, #2 ... from top to bottom, then left to right.)
C251  VAL1: 2.2uF(K)  SIZECODESMD: 2012  (hidden comment: GRM21BC71E106KE01)
C252  VAL1: 1uF(M)  VAL2: 25V  SIZECODESMD: 1005  (hidden comment: C)
C253  VAL1: 100nF(K)  VAL2: 25V  SIZECODESMD: 1005  (hidden comment: C)
C254  VAL1: 1uF(M)  VAL2: 25V  SIZECODESMD: 1005  (hidden comment: C)
C255  VAL1: 1nF(K)  VAL2: 50V  SIZECODESMD: 1005  (hidden comment: C)
C256  VAL1: 3.3nF(K)  VAL2: 50V  SIZECODESMD: 1005  (hidden comment: C)
C257  VAL1: 330pF(J)  VAL2: 50V  SIZECODESMD: 1005  (hidden comment: C)
C258  NOTMOUNT: NOT MOUNT  SIZECODESMD: 3216  (hidden comment: C)
DP251  TP  (value not drawn)
DP252  VAL3: HK-2-S  (hidden comment: TP)
DP253  VAL3: HK-2-S  (hidden comment: TP)
DP254  VAL3: HK-2-S  (hidden comment: TP)
DP255  VAL3: HK-2-S  (hidden comment: TP)
DP256  VAL3: HK-2-S  (hidden comment: TP)
DP257  VAL3: HK-2-S  (hidden comment: TP)
DP258  VAL3: LC-22-S-BLACK  (hidden comment: TP)
DP259  TP  (value not drawn)
DP260  TP  (value not drawn)
DP261  TP  (value not drawn)
IC251  VAL3: UCC28951  (hidden comment: L28950)
R252  VAL1: 13k(F)  SIZECODESMD: 1005  (hidden comment: R)
R253  VAL1: 15k(F)  SIZECODESMD: 1005  (hidden comment: R)
R254  VAL1: 90k(J)  SIZECODESMD: 1005  (hidden comment: R)
R255  VAL1: 18k(F)  SIZECODESMD: 1005  (hidden comment: R)
R256  VAL1: 22(J)  SIZECODESMD: 1005  (hidden comment: R)
R257  VAL1: 47k(F)  SIZECODESMD: 1005  (hidden comment: R)
R258  VAL1: 33k(F)  SIZECODESMD: 1005  (hidden comment: R)
R259  VAL1: 12k(F)  SIZECODESMD: 1005  (hidden comment: R)
R260  VAL1: 220(J)  SIZECODESMD: 1005  (hidden comment: R)
R261  VAL1: 6.8k(J)  SIZECODESMD: 1005  (hidden comment: R)
R262  NOTMOUNT: NOT MOUNT  SIZECODESMD: 1005  (hidden comment: R)
R263  NOTMOUNT: NOT MOUNT  SIZECODESMD: 1005  (hidden comment: R)
R264  VAL1: 6.8k(J)  SIZECODESMD: 1005  (hidden comment: R)
R265  VAL1: 6.8k(J)  SIZECODESMD: 1005  (hidden comment: R)
R266  VAL1: 2.2k(F)  SIZECODESMD: 1005  (hidden comment: R)
R267  VAL1: 2.2k(F)  SIZECODESMD: 1005  (hidden comment: R)
R268  VAL1: 0  SIZECODESMD: 1005  (hidden comment: R)
R269  NOTMOUNT: NOT MOUNT  SIZECODESMD: 1005  (hidden comment: R)
R270  VAL1: 0  SIZECODESMD: 1005  (hidden comment: R)
R271  VAL1: 18k(J)  SIZECODESMD: 1005  (hidden comment: R)
R272  VAL1: 430(J)  SIZECODESMD: 1005  (hidden comment: R)
R273  VAL1: 680(J)  SIZECODESMD: 1005  (hidden comment: R)
R274  VAL1: 33(J)  SIZECODESMD: 3216  (hidden comment: R)
R275  VAL1: 33(J)  SIZECODESMD: 3216  (hidden comment: R)
R276  VAL1: 33(J)  SIZECODESMD: 3216  (hidden comment: R)
R277  NOTMOUNT: NOT MOUNT  SIZECODESMD: 1005  (hidden comment: R)
R278  VAL1: 36k(F)  SIZECODESMD: 1005  (hidden comment: R)
R279  VAL1: 6.8k(D)  SIZECODESMD: 1005  (hidden comment: R)
R280  VAL1: 22k(D)  SIZECODESMD: 1005  (hidden comment: R)
R281  VAL1: 22k(D)  SIZECODESMD: 1005  (hidden comment: R)
R282  VAL1: 2.2k(D)  SIZECODESMD: 1005  (hidden comment: R)
R283  VAL1: 470(D)  SIZECODESMD: 1005  (hidden comment: R)
R284  NOTMOUNT: NOT MOUNT  SIZECODESMD: 3216  (hidden comment: R)
U?#4  DATE: 2025/09/24  DRAWINGNUMBER: RD244-SCHEMATIC1-01 / RD265-SCHEMATIC1-01 / RD266-SCHEMATIC1-01  TITLE: 3kW Power Supply for Servers and Telecoms Using Surface-Mounted SiC MOSFET / 3kW Power Supply for AI Servers Using Surface-Mounted SiC MOSFET / 3kW Power Supply for Electric Scooter Fast Chargers Using SiC MOSFET  FUNCTION: PSFB Controller  SHEETNUMBER: 4/7  REVISION: 01  (hidden comment: WAKU_DEF_A3_1)

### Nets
LGND: C251.1 C252.1 C253.1 C254.1 C255.1 DP258.1 IC251.24 R252.1 R253.1 R254.1 R255.1 R257.1 R261.1 R264.1 R267.1 R272.1 R274.1 R275.1 R276.1 R277.1 R283.1
VCC12R0_2: R256.1
VREF_PSFB: C254.2 IC251.1 R258.2 R262.2 R263.2 R266.2 R270.2
CS: R273.2 R274.2 R275.2 R276.2 ; off-sheet CS
OUTA2: DP252.1 IC251.22 ; off-sheet OUTA2
OUTB2: DP253.1 IC251.21 ; off-sheet OUTB2
OUTC2: DP254.1 IC251.20 ; off-sheet OUTC2
OUTD2: DP255.1 IC251.19 ; off-sheet OUTD2
OUTE: DP256.1 IC251.18 ; off-sheet OUTE
OUTF: DP257.1 IC251.17 ; off-sheet OUTF
PSFB_OUT: R279.2 ; off-sheet PSFB_OUT
SIG00429: C256.1 R278.1
SIG00430: R268.2 R269.2 R273.1
SIG00431: IC251.11 R257.2
SIG00432: C252.2 C253.2 IC251.23 R256.2
SIG00433: IC251.9 R255.2
SIG00434: C255.2 DP259.1 IC251.15 R260.2 R265.2 R268.1
SIG00435: R280.1 R281.2
SIG00436: IC251.8 R254.2
SIG00437: IC251.7 R253.2
SIG00438: IC251.6 R252.2
SIG00439: C258.2 R284.1
SIG00440: R282.1 R283.2
SIG00441: R258.1 R259.2
SIG00442: IC251.10 R259.1
SIG00443: DP260.1 IC251.2 R266.1 R267.2
SIG00444: IC251.14 R263.1 R264.2 R265.1
SIG00445: IC251.13 R260.1 R261.2 R262.1
SIG00446: C257.1 C258.1 DP261.1 IC251.3 R278.2 R281.1 R282.2
SIG00447: R279.1 R280.2 R284.2
SIG00448: C256.2 C257.2 IC251.4 R277.2
SIG00449: R269.1 R270.1 R271.2
SIG00450: IC251.12 R271.1 R272.2
SS/EN: C251.2 DP251.1 IC251.5 ; off-sheet SS/EN

Not connected (* = marked no-connect by the designer): IC251 16

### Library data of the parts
C251 = GRM21BC71E106KE01: TIME: 10:25:11; UPDATEUSER: t4887876; UPDATETIME: 16:23:00; SAVECOUNT: 11; VAL2: 25V; MAKER: Murata; OriginalSymbolOrigin: (2540,7620); CHIPSIZE: 1005; MAXGCOUNT: 1
C252-C255 = C_Dup2: as C11 on sheet 1
C256 = C_Dup2: SQ_PART_MODEL: CON_5.6N; OriginalSymbolOrigin: (2540,7620); COMP: PRT_52; MAXGCOUNT: 1; ADSCNVFLAG: ON; ADSCOMPONENTNAME: C_1005; SAVECOUNT: 0
C257 = C_Dup2: SQ_PART_MODEL: CON_560P; OriginalSymbolOrigin: (2540,7620); COMP: PRT_52; MAXGCOUNT: 1; ADSCNVFLAG: ON; ADSCOMPONENTNAME: C_1005; SAVECOUNT: 0
C258 = C_Dup2: VAL1: 10uF(K); VAL2: 25V; OriginalSymbolOrigin: (2540,7620); COMP: PRT_46; MAXGCOUNT: 1; SAVECOUNT: 0
DP251 DP259-DP261 = TP: as DP51 on sheet 2
DP252-DP257 = TP: as DP56 on sheet 2
DP258 = TP: TIME: 16:12:21; UPDATEUSER: fukuda-y; UPDATETIME: 16:18:11; SAVECOUNT: 2; SAVEAREA0: -242,-92,12810,7836; OriginalSymbolOrigin: (0,7620); COMP: PRT_34
IC251 = L28950: SAVEAREA0: -25263,1478,86635,87004; SAVECOUNT: 35; TIME: 15:02:55; UPDATEUSER: cae; UPDATETIME: 16:32:09; OriginalSymbolOrigin: (7620,83820); COMP: PRT_16
R252-R254 R256-R259 R261 R264 R266 R267 R271-R273 R278-R283 = R_Dup2: as R52 on sheet 2
R255 = R_Dup2: SQ_PART_MODEL: RES_15K; VAL2: 63mW; OriginalSymbolOrigin: (5080,5080); COMP: GDM010004481; CHIPSIZE: 1608; MAXGCOUNT: 1; ADSCNVFLAG: ON; ADSCOMPONENTNAME: R_1608; SAVECOUNT: 0
R260 R265 = R_Dup2: VAL2: 63mW; OriginalSymbolOrigin: (5080,5080); COMP: GDM010004481; CHIPSIZE: 1608; MAXGCOUNT: 1; ADSCOMPONENTNAME: R_1005; SAVECOUNT: 0
R262 R263 = R_Dup2: VAL2: 63mW; VAL1: 6.8k(J); OriginalSymbolOrigin: (5080,5080); COMP: GDM010004481; CHIPSIZE: 1608; MAXGCOUNT: 1; ADSCOMPONENTNAME: R_1005; SAVECOUNT: 0
R268 = R_Dup2: SQ_PART_MODEL: RES_0; VAL2: 63mW; OriginalSymbolOrigin: (5080,5080); COMP: GDM010004481; CHIPSIZE: 1608; MAXGCOUNT: 1; ADSCNVFLAG: ON; ADSCOMPONENTNAME: R_1608
R269 R277 = R_Dup2: VAL2: 63mW; VAL1: 0; OriginalSymbolOrigin: (5080,5080); COMP: GDM010004481; CHIPSIZE: 1608; MAXGCOUNT: 1
R270 = R_Dup2: VAL2: 63mW; OriginalSymbolOrigin: (5080,5080); COMP: GDM010004481; CHIPSIZE: 1608; MAXGCOUNT: 1
R274-R276 = R_Dup2: VAL2: 250mW; OriginalSymbolOrigin: (5080,5080); COMP: PRT_5; MAXGCOUNT: 1; SAVECOUNT: 0
R284 = R_Dup2: VAL2: 250mW; VAL1: 36(J); OriginalSymbolOrigin: (5080,5080); COMP: PRT_5; MAXGCOUNT: 1; SAVECOUNT: 0
U?#4 = WAKU_DEF_A3_1: PLOTTIME: HH:MM; SAVEAREA0: 96913,-567914,509243,-368858; TIME: 16:14:05; UPDATEUSER: t5459927; UPDATETIME: 13:12:48; SAVECOUNT: 3; ZONEOFFSETX: 36; ZONEOFFSETY: -24; OriginalSymbolOrigin: (12700,-12700); SHTSAVECOUNT: 142; PAGENUMBER: 4; DESIGNED: TOSHIBA

## Sheet 5.SchDoc
size 609 x 444 mm
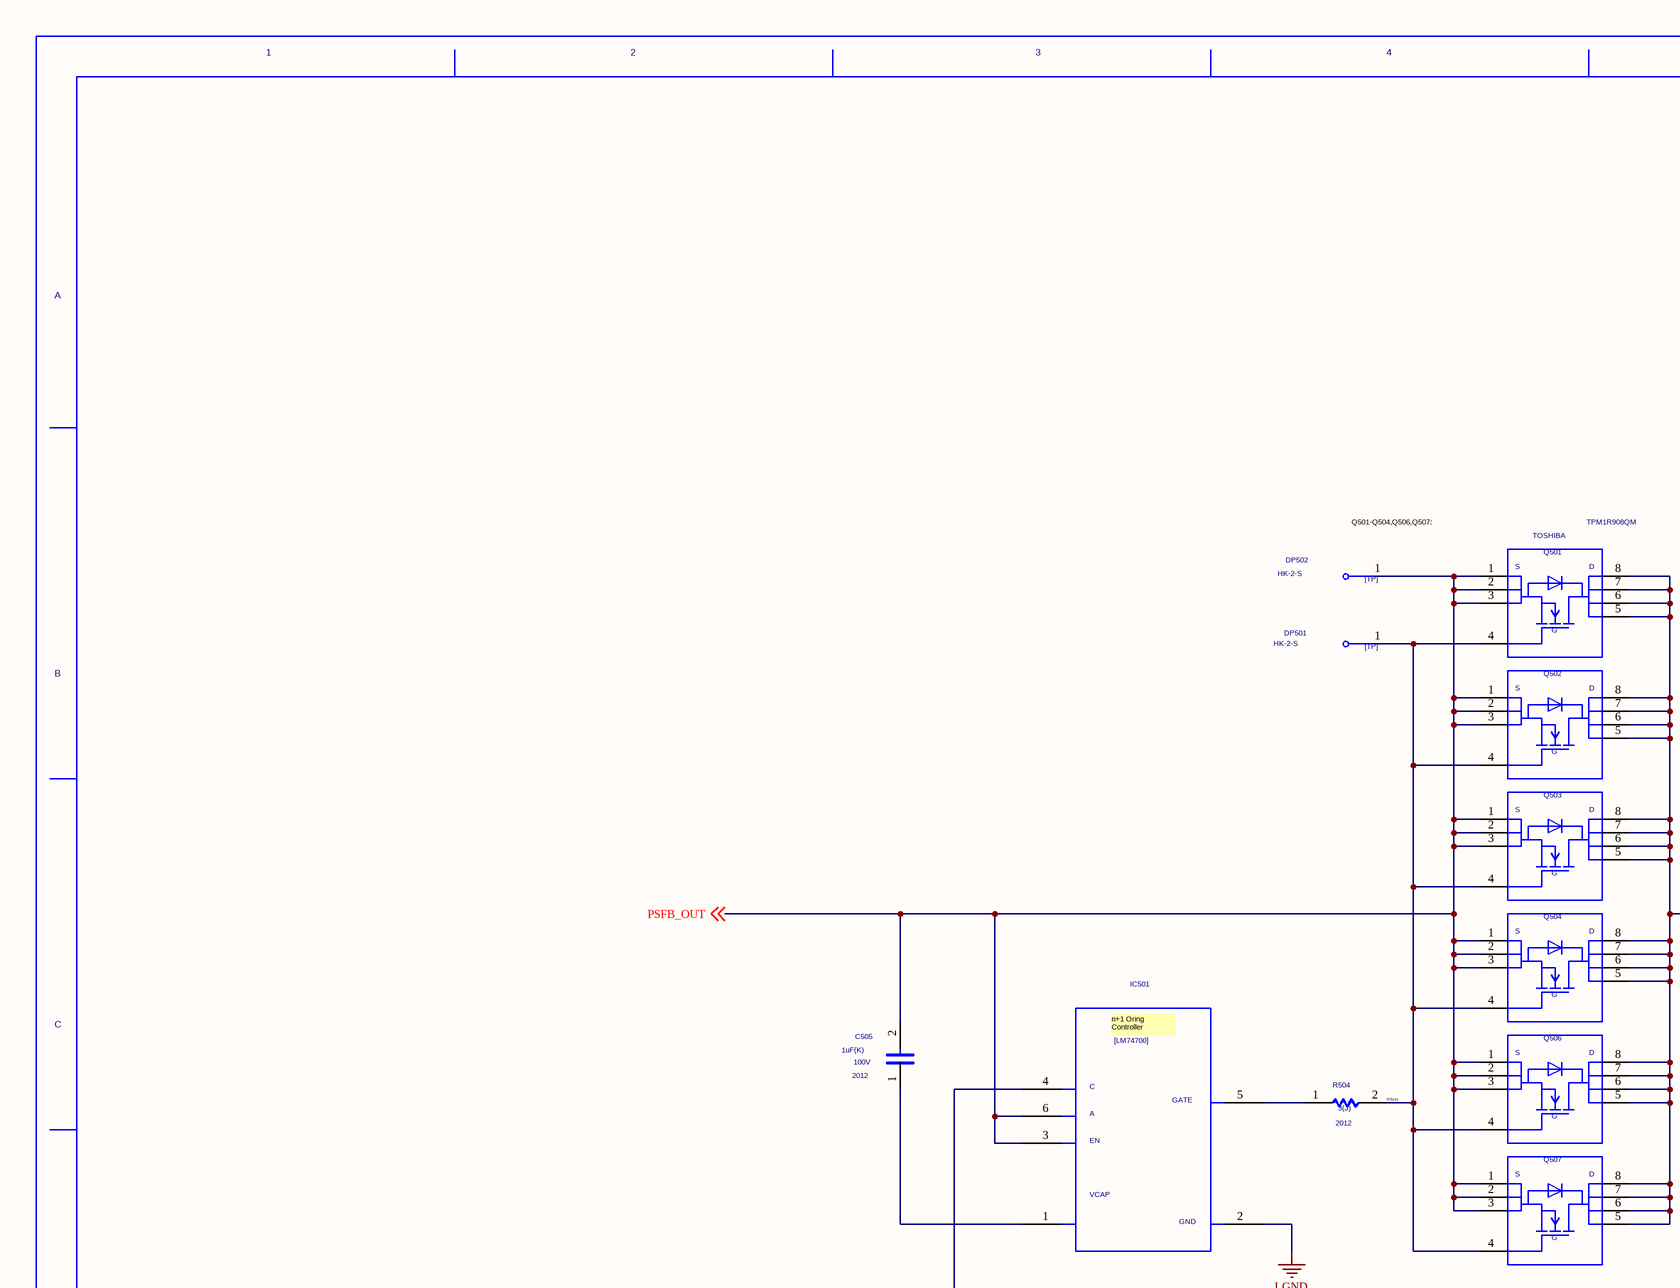
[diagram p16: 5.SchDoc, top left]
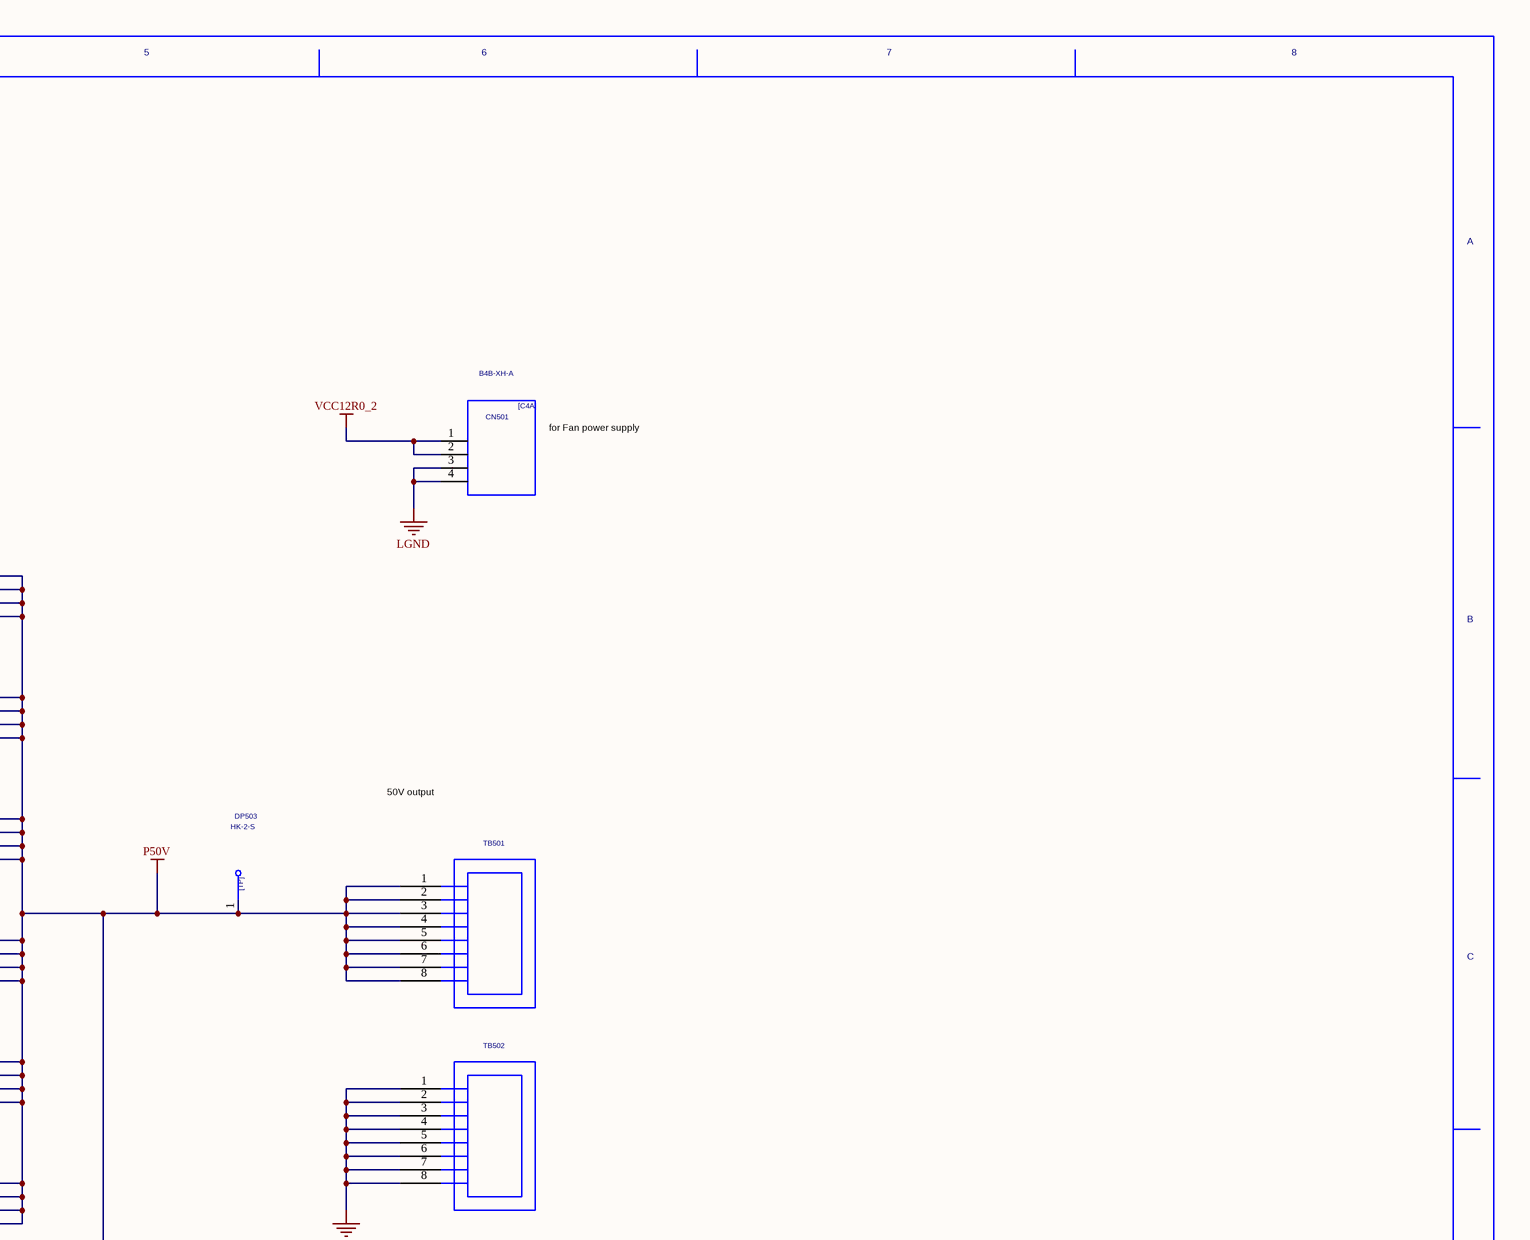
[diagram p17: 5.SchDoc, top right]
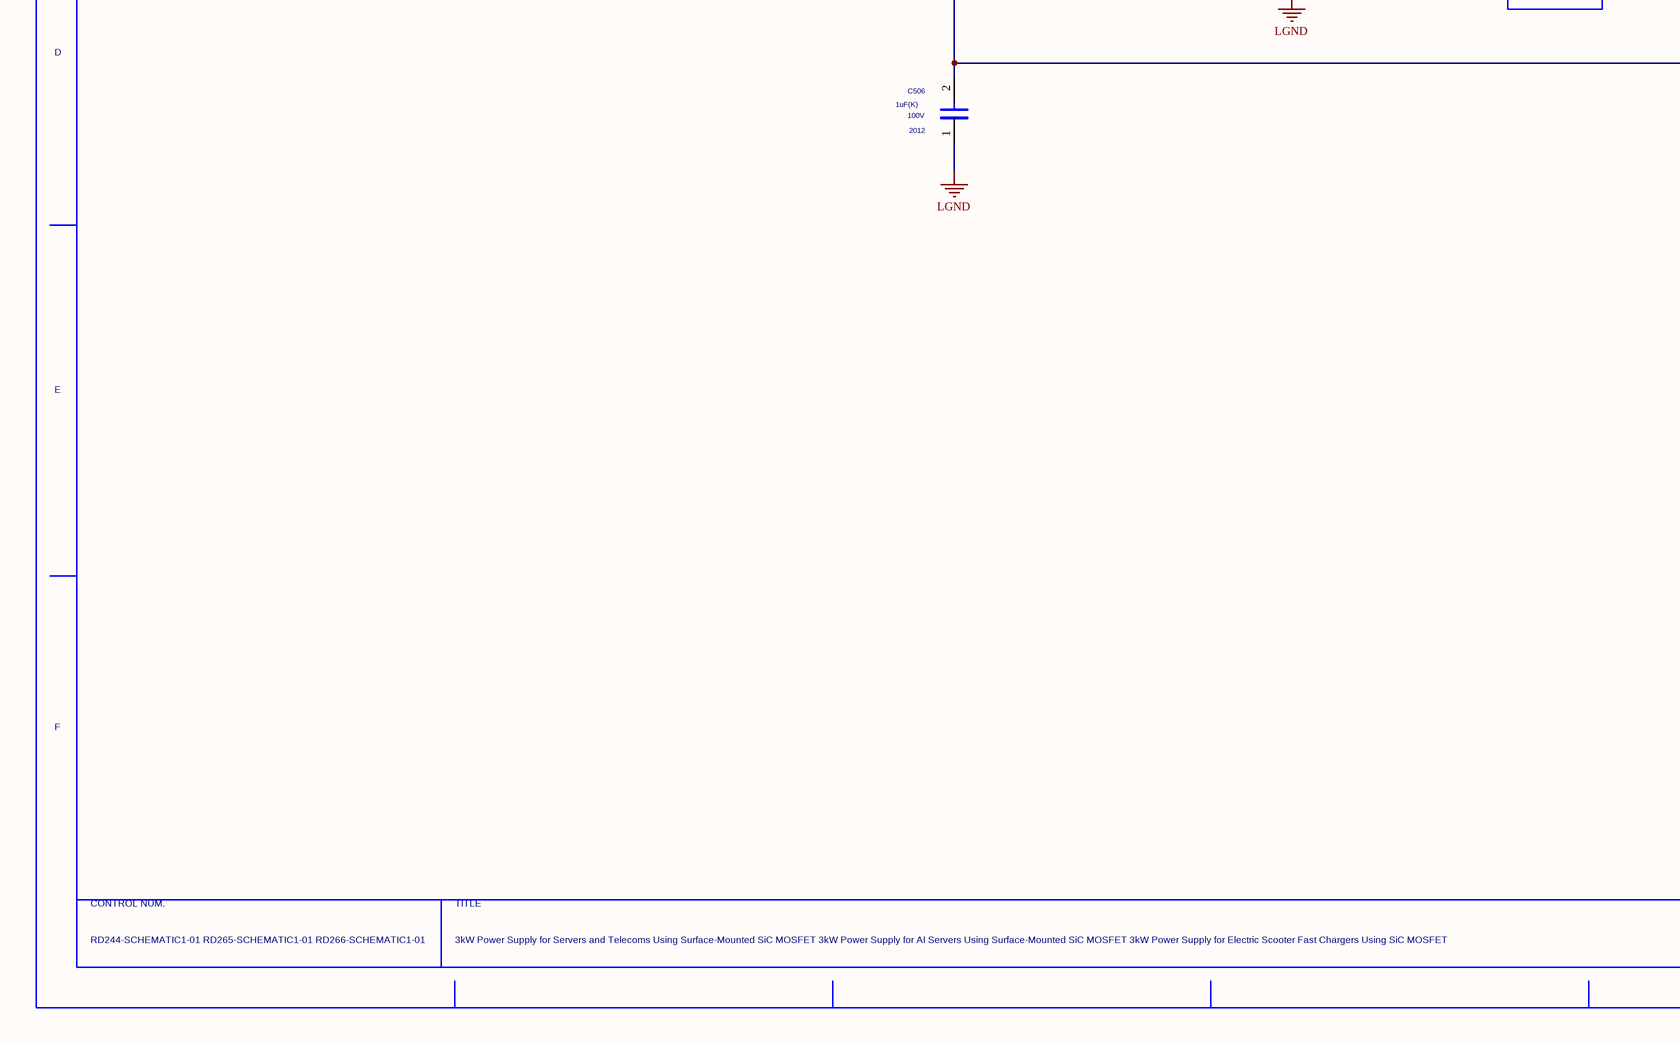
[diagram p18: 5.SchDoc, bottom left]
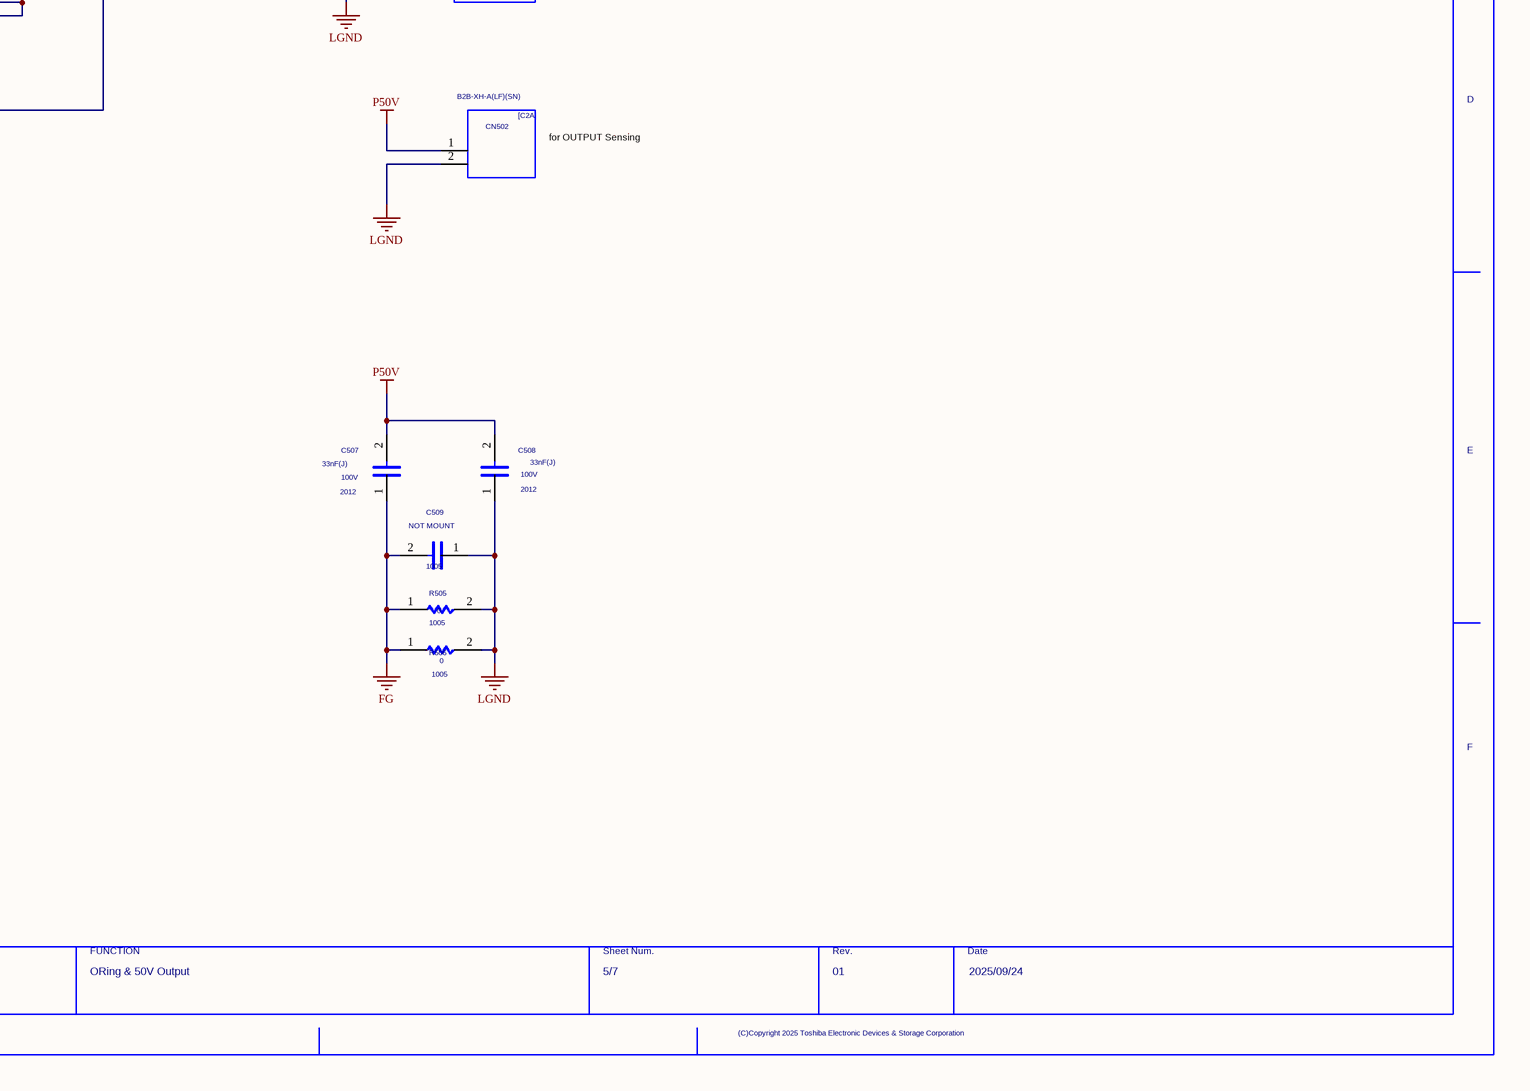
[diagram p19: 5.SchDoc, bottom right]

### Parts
(Parts that share a designator on the sheet are numbered #1, #2 ... from top to bottom, then left to right.)
C505  VAL1: 1uF(K)  VAL2: 100V  SIZECODESMD: 2012  (hidden comment: GRM21BC71E106KE01)
C506  VAL1: 1uF(K)  VAL2: 100V  SIZECODESMD: 2012  (hidden comment: GRM21BC71E106KE01)
C507  VAL1: 33nF(J)  VAL2: 100V  SIZECODESMD: 2012  (hidden comment: GRM21BC71E106KE01)
C508  VAL1: 33nF(J)  VAL2: 100V  SIZECODESMD: 2012  (hidden comment: GRM21BC71E106KE01)
C509  NOTMOUNT: NOT MOUNT  SIZECODESMD: 1005  (hidden comment: C)
CN501  VAL3: B4B-XH-A  (hidden comment: C4A)
CN502  VAL3: B2B-XH-A(LF)(SN)  (hidden comment: C2A)
DP501  VAL3: HK-2-S  (hidden comment: TP)
DP502  VAL3: HK-2-S  (hidden comment: TP)
DP503  VAL3: HK-2-S  (hidden comment: TP)
IC501  LM74700-Q1  (value not drawn)
Q501  VAL3: TPM1R908QM  USERCOMPTEXT3: TOSHIBA  (hidden comment: NCHMOSFET_SOPADVANCE-E-01)
Q502  NCHMOSFET_SOPADVANCE-E-01  (value not drawn)
Q503  NCHMOSFET_SOPADVANCE-E-01  (value not drawn)
Q504  NCHMOSFET_SOPADVANCE-E-01  (value not drawn)
Q506  NCHMOSFET_SOPADVANCE-E-01  (value not drawn)
Q507  NCHMOSFET_SOPADVANCE-E-01  (value not drawn)
R504  VAL1: 3(J)  SIZECODESMD: 2012  (hidden comment: R)
R505  VAL1: 0  SIZECODESMD: 1005  (hidden comment: R)
R506  VAL1: 0  SIZECODESMD: 1005  (hidden comment: R)
TB501  7460305  (value not drawn)
TB502  7460305  (value not drawn)
U?#5  DATE: 2025/09/24  DRAWINGNUMBER: RD244-SCHEMATIC1-01 / RD265-SCHEMATIC1-01 / RD266-SCHEMATIC1-01  TITLE: 3kW Power Supply for Servers and Telecoms Using Surface-Mounted SiC MOSFET / 3kW Power Supply for AI Servers Using Surface-Mounted SiC MOSFET / 3kW Power Supply for Electric Scooter Fast Chargers Using SiC MOSFET  FUNCTION: ORing & 50V Output  SHEETNUMBER: 5/7  REVISION: 01  (hidden comment: WAKU_DEF_A3_1)

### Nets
FG: C507.1 C509.2 R505.1 R506.1
LGND: C506.1 C508.1 C509.1 CN501.3 CN501.4 CN502.2 IC501.2 R505.2 R506.2 TB502.1 TB502.2 TB502.3 TB502.4 TB502.5 TB502.6 TB502.7 TB502.8
P50V: C506.2 C507.2 C508.2 CN502.1 DP503.1 IC501.4 Q501.5 Q501.6 Q501.7 Q501.8 Q502.5 Q502.6 Q502.7 Q502.8 Q503.5 Q503.6 Q503.7 Q503.8 Q504.5 Q504.6 Q504.7 Q504.8 Q506.5 Q506.6 Q506.7 Q506.8 Q507.5 Q507.6 Q507.7 Q507.8 TB501.1 TB501.2 TB501.3 TB501.4 TB501.5 TB501.6 TB501.7 TB501.8
VCC12R0_2: CN501.1 CN501.2
PSFB_OUT: C505.2 DP502.1 IC501.3 IC501.6 Q501.1 Q501.2 Q501.3 Q502.1 Q502.2 Q502.3 Q503.1 Q503.2 Q503.3 Q504.1 Q504.2 Q504.3 Q506.1 Q506.2 Q506.3 Q507.1 Q507.2 Q507.3 ; off-sheet PSFB_OUT
SIG122: C505.1 IC501.1
SIG136: IC501.5 R504.1
SIG141: DP501.1 Q501.4 Q502.4 Q503.4 Q504.4 Q506.4 Q507.4 R504.2

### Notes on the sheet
- for Fan power supply
- (near DP502) Q501-Q504,Q506,Q507:
- 50V output
- for OUTPUT Sensing

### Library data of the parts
C505-C508 = GRM21BC71E106KE01: as C69 on sheet 2
C509 = C_Dup2: as C62 on sheet 2
CN501 = C4A: SAVEAREA0: -8845,-265,28754,23475; SAVECOUNT: 22; TIME: 13:28:28; UPDATEUSER: tomizawa-y; UPDATETIME: 15:03:27; OriginalSymbolOrigin: (2540,20320); USERCOMPTEXT3: ローカライズ; COMPONENTNAME: K22S0019_package; MAXGCOUNT: 1; COMP: K22S0019; ADSCNVFLAG: ON
CN502 = C2A: OUMEPARTTYPE2: CN; SAVEAREA0: -4611,-206,24632,18258; SAVECOUNT: 25; TIME: 13:28:28; UPDATEUSER: tomizawa-y; UPDATETIME: 12:08:31; OriginalSymbolOrigin: (2540,15240); USERCOMPTEXT3: ローカライズ; COMPONENTNAME: K2203993_package; MAXGCOUNT: 1; COMP: K2203993; ADSCNVFLAG: ON
DP501-DP503 = TP: as DP56 on sheet 2
IC501 = LM74700-Q1: SAVEAREA0: -16399,-622,62276,51274; TIME: 11:49:52; UPDATEUSER: t4887876; UPDATETIME: 18:16:17; SAVECOUNT: 39; OriginalSymbolOrigin: (7620,48260)
Q501 = NCHMOSFET_SOPADVANCE-E-01: TIME: 18:29:30; UPDATEUSER: t4887876; UPDATETIME: 14:15:50; SAVECOUNT: 30; SAVEAREA0: -10143,-336,37609,28718; COMP: NchMOSFET_SOPAdvance(E)-01; VAL1: 80V; VAL2: **A; CHIPSET: ※型名を記入する; OriginalSymbolOrigin: (5080,22860); MAXGCOUNT: 1
Q502-Q504 Q506 Q507 = NCHMOSFET_SOPADVANCE-E-01: TIME: 18:29:30; UPDATEUSER: t4887876; UPDATETIME: 14:15:50; SAVECOUNT: 30; SAVEAREA0: -10143,-336,37609,28718; COMP: NchMOSFET_SOPAdvance(E)-01; VAL3: TPM1R908QM; VAL1: 80V; VAL2: **A; CHIPSET: ※型名を記入する; OriginalSymbolOrigin: (5080,22860); MAXGCOUNT: 1; USERCOMPTEXT3: TOSHIBA
R504 = R_Dup2: VAL2: 250mW; OriginalSymbolOrigin: (5080,5080); COMP: R2012; CHIPSIZE: 1608; MAXGCOUNT: 1; SAVECOUNT: 0
R505 R506 = R_Dup2: as R270 on sheet 4
TB501 TB502 = 7460305: SAVEAREA0: -4578,-286,40174,28213; SAVECOUNT: 17; TIME: 14:53:12; UPDATEUSER: t4887876; UPDATETIME: 16:00:29; VAL2: 160Amax; VAL1: M5; OriginalSymbolOrigin: (7620,27940); USERCOMPTEXT1: Wurth; MAXGCOUNT: 1; ADSCNVFLAG: ON
U?#5 = WAKU_DEF_A3_1: PLOTTIME: HH:MM; SAVEAREA0: 96913,-567914,509243,-368858; TIME: 12:01:09; UPDATEUSER: t5459927; UPDATETIME: 13:12:48; SAVECOUNT: 3; ZONEOFFSETX: 36; ZONEOFFSETY: -24; OriginalSymbolOrigin: (12700,-12700); SHTSAVECOUNT: 121; PAGENUMBER: 5; DESIGNED: TOSHIBA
